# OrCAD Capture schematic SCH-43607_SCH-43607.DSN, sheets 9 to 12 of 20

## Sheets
9 P09_CPU POWER2: size C
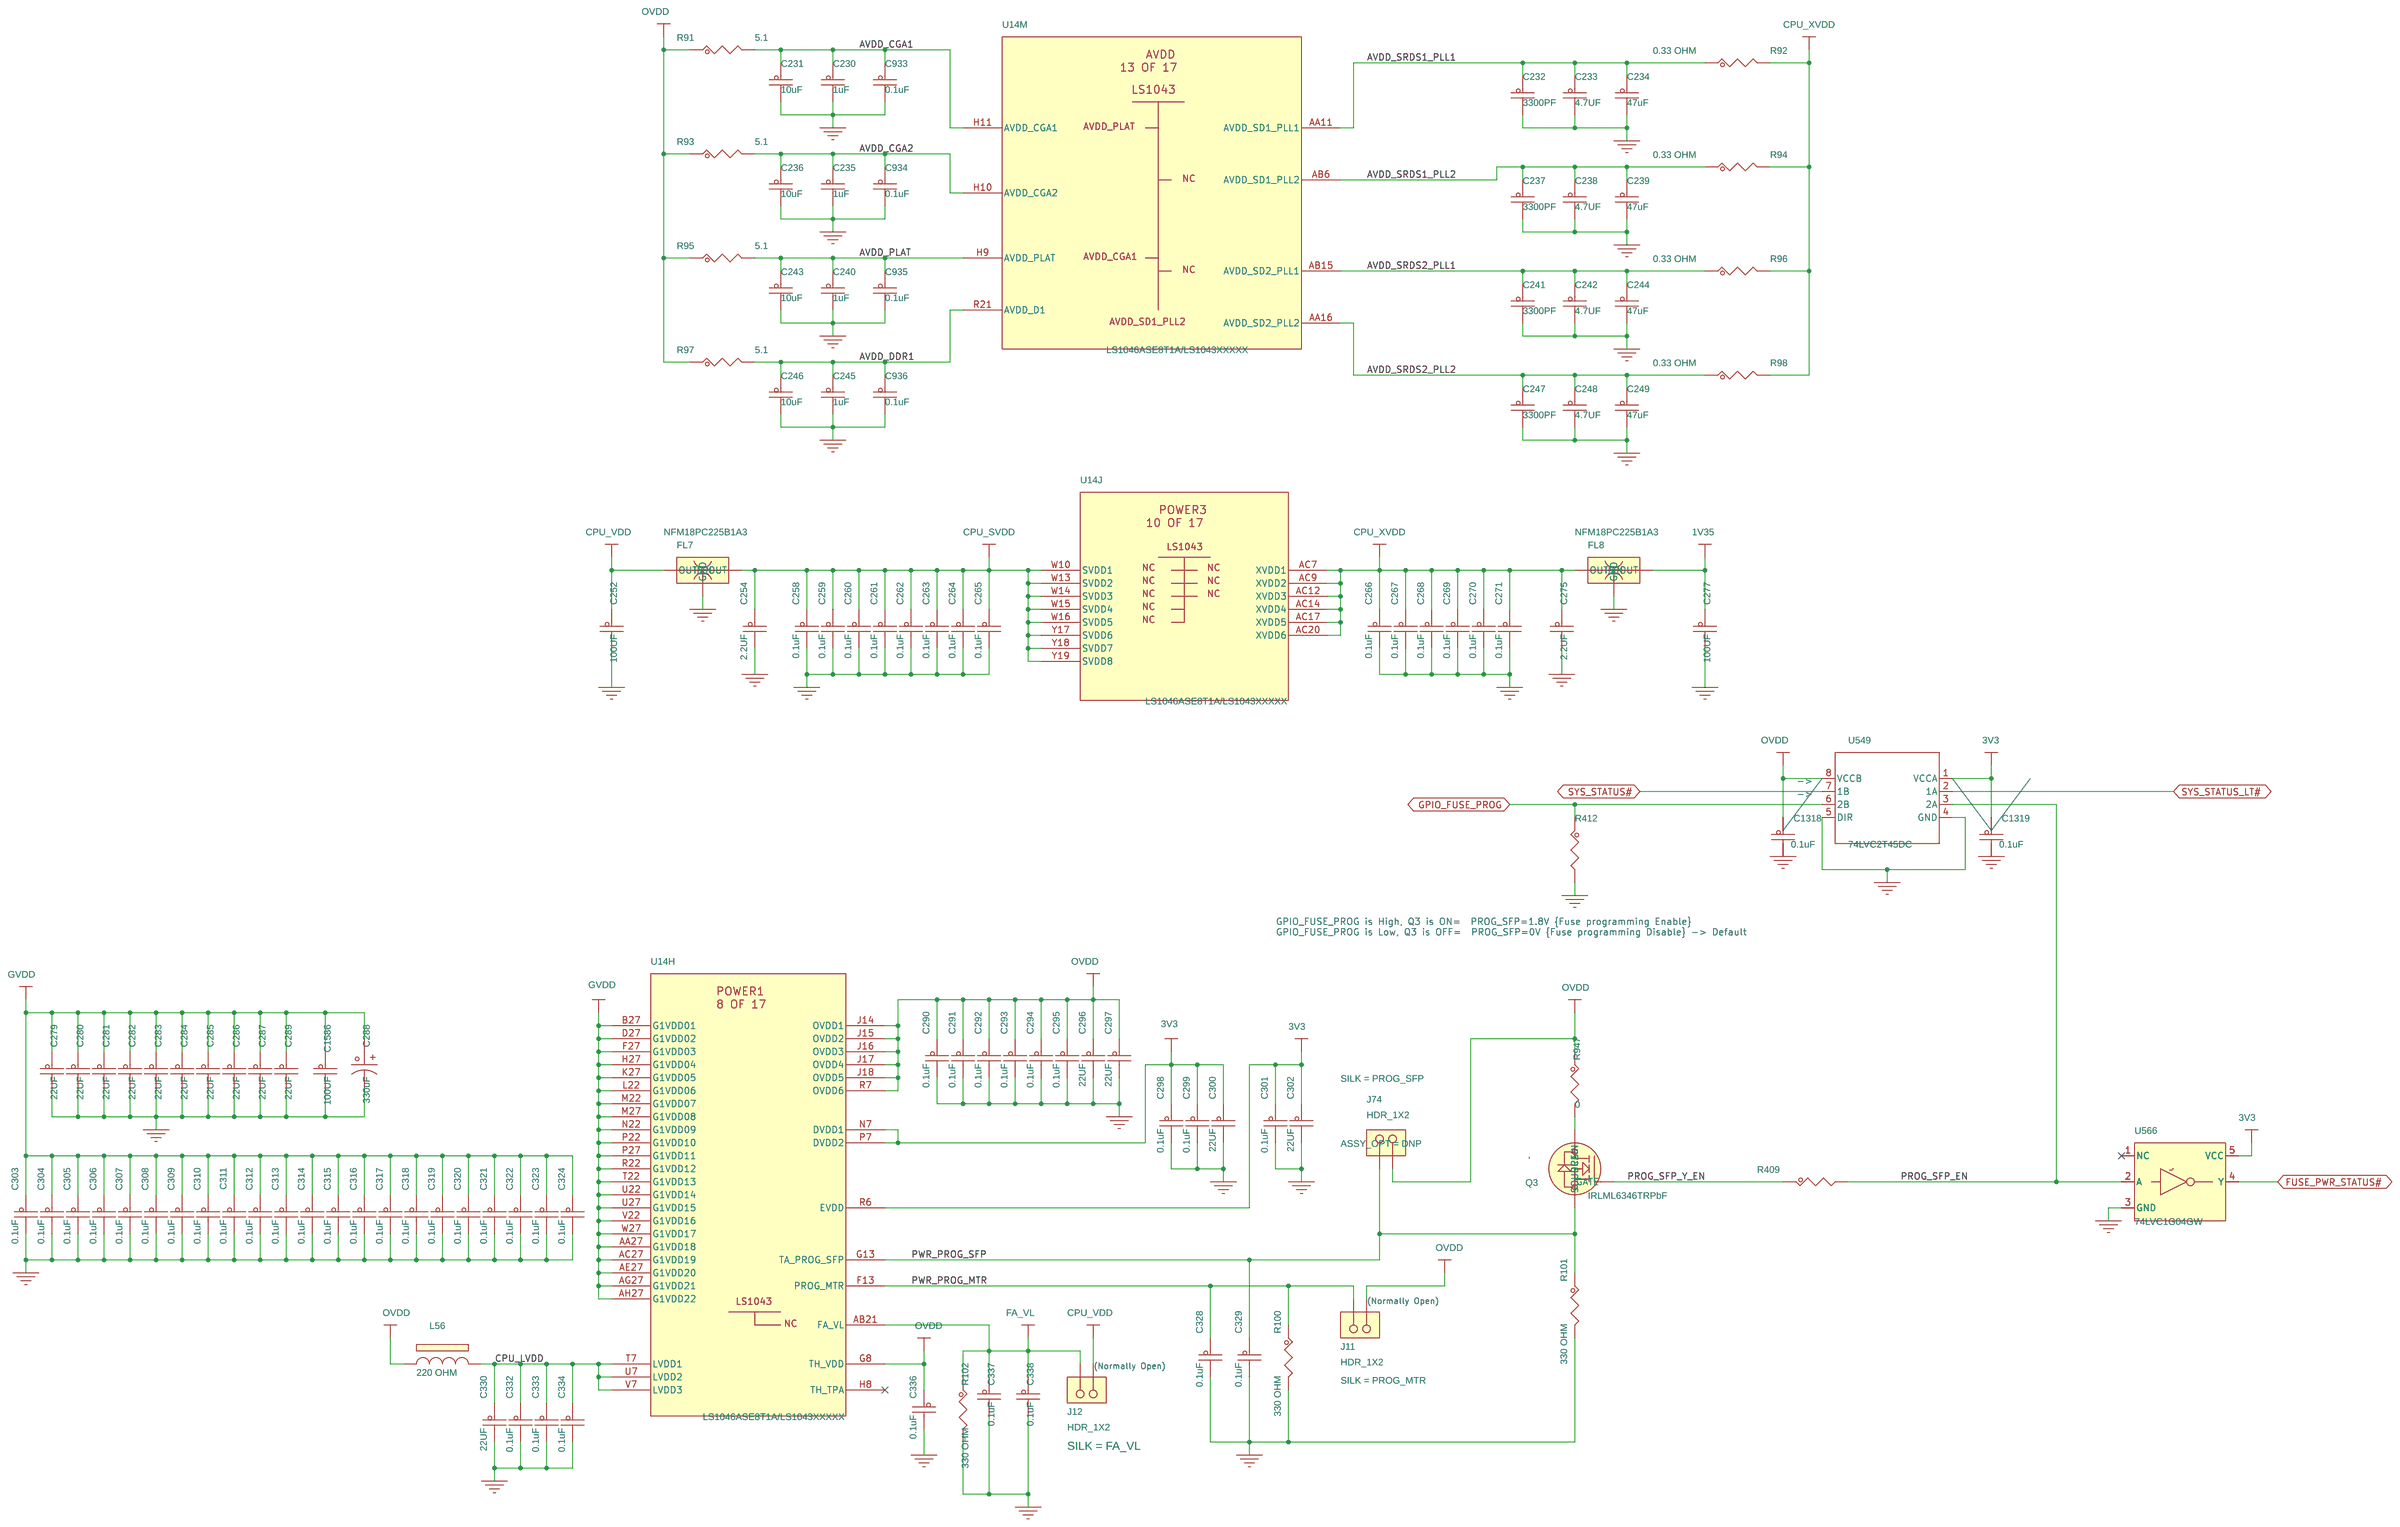
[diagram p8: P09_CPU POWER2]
10 P10_CPU DDR4 CTRL & SDRAM PART1: size C
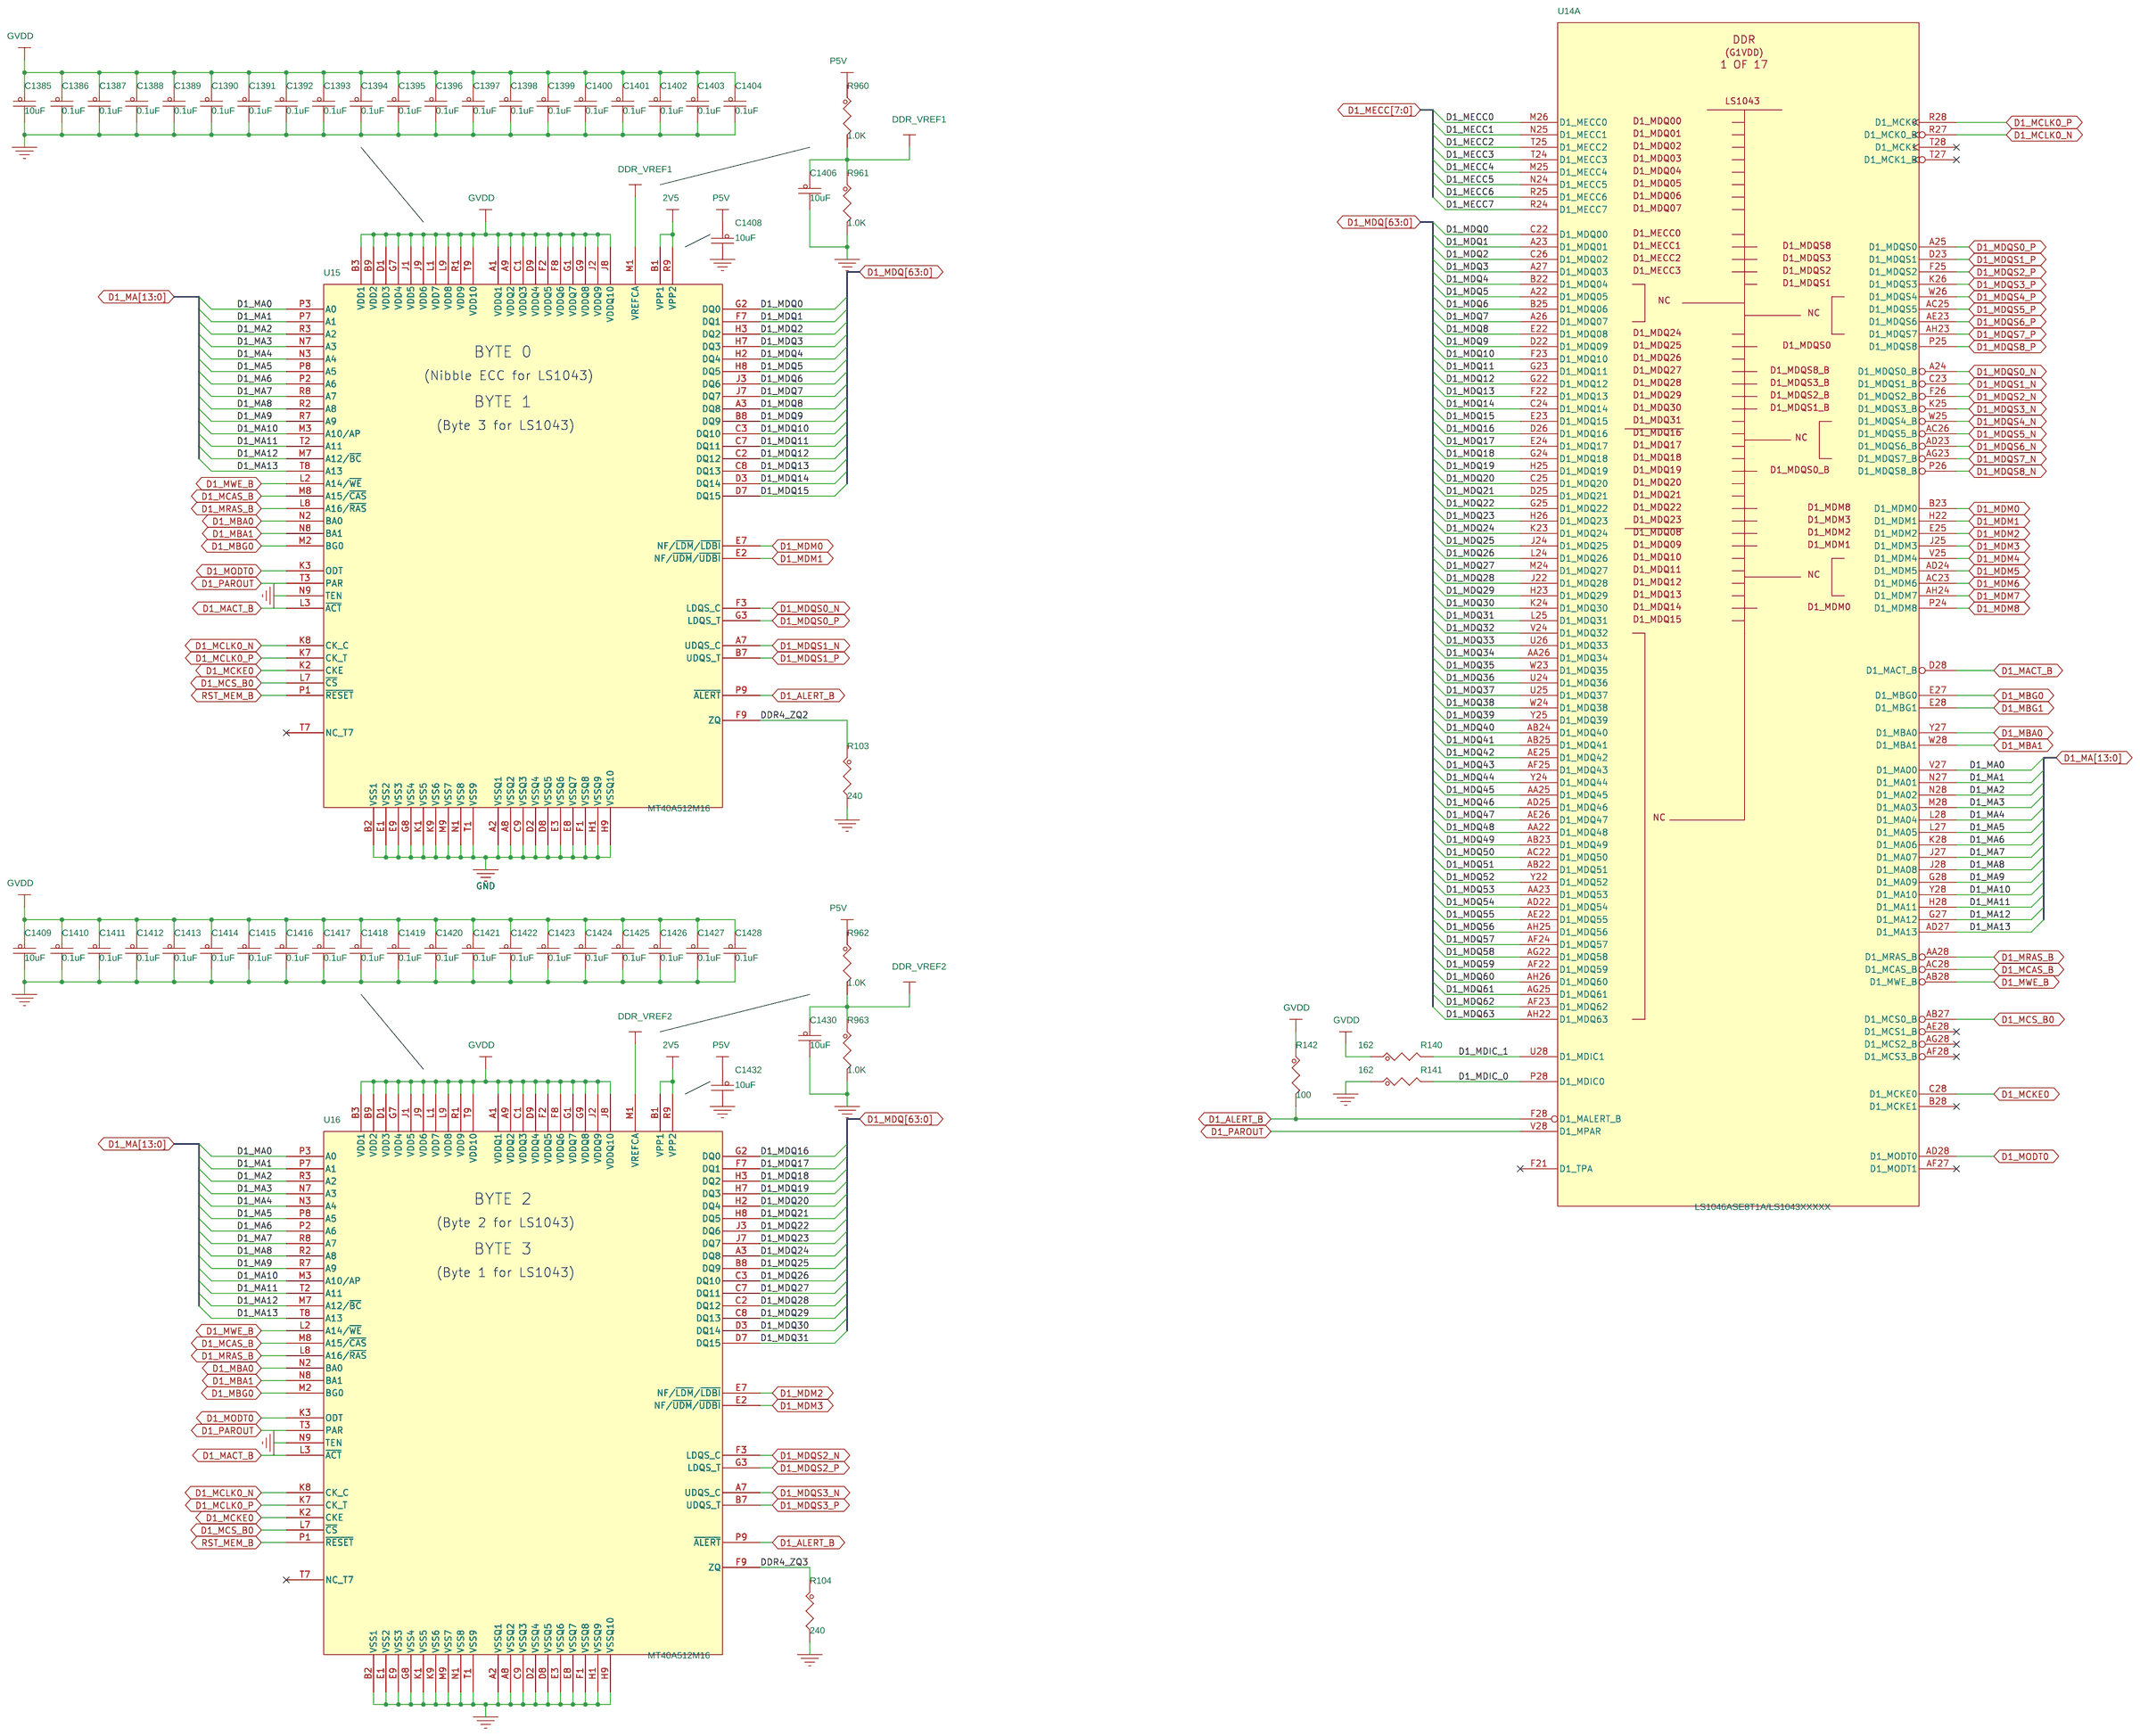
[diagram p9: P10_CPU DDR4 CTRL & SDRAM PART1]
11 P11_DDR4 SDRAM PART2: size C
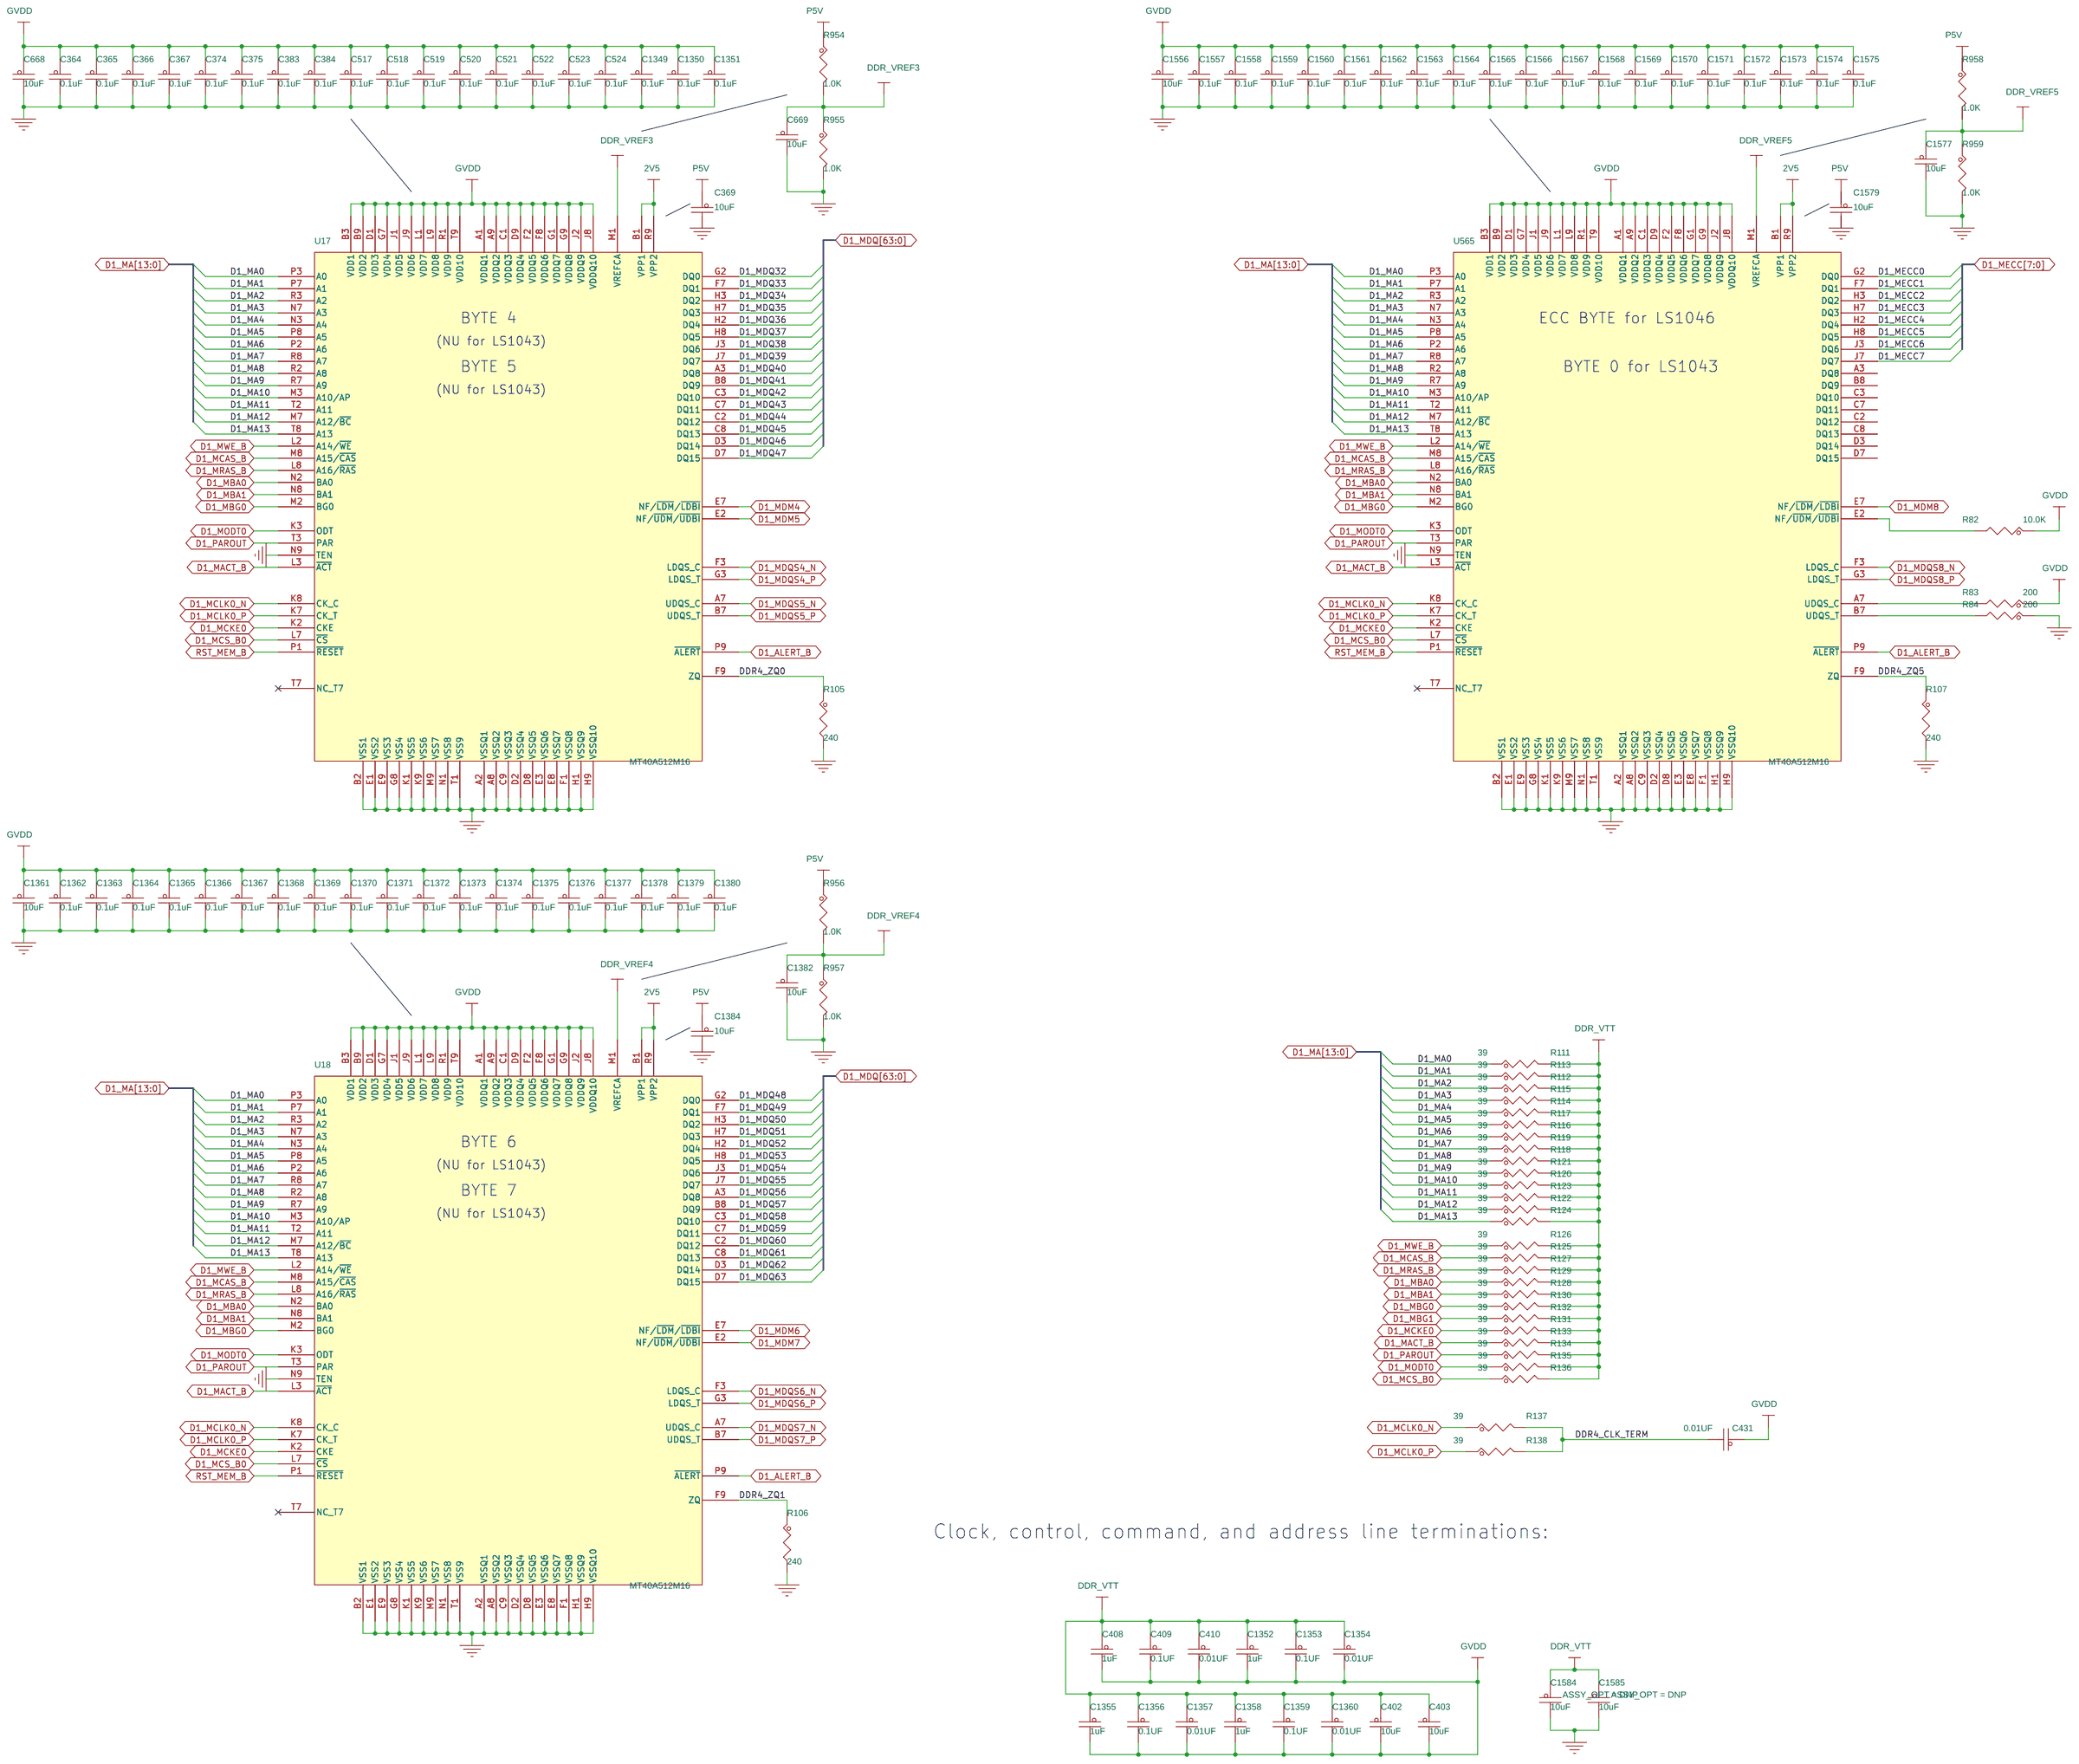
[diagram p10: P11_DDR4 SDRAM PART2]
12 P12_CPU_QSPI & NAND: size C
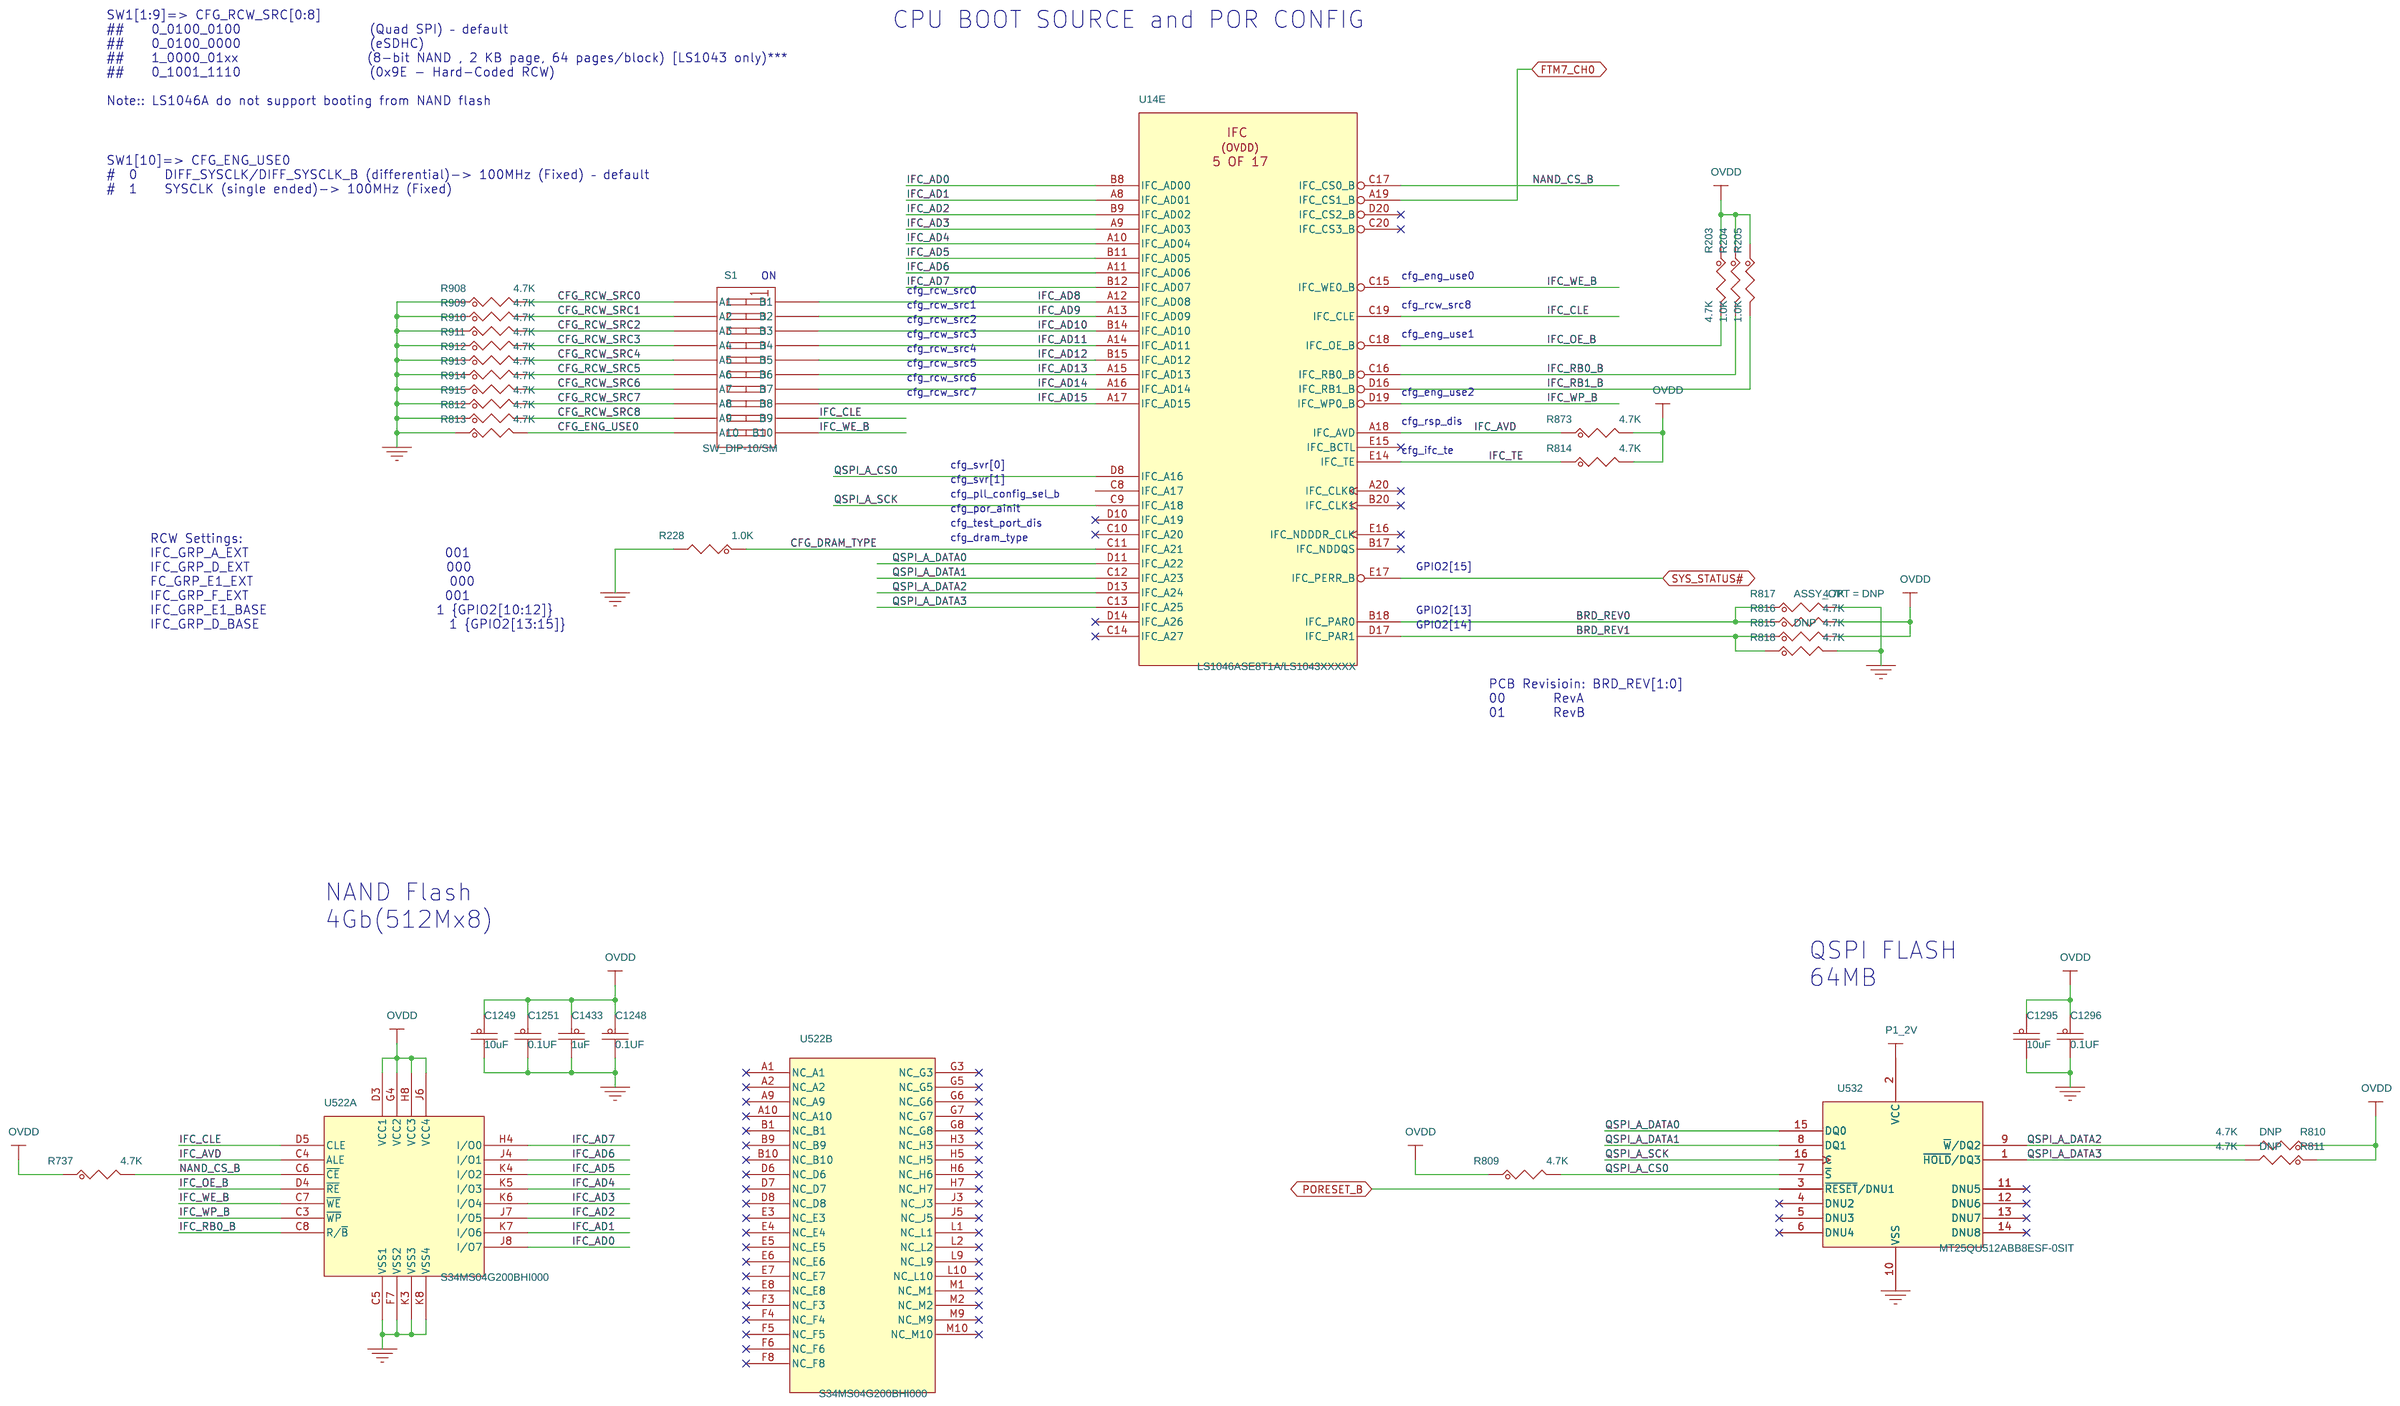
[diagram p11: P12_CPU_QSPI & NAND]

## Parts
sheet P09_CPU POWER2
C230  1uF  [CC0402_25]
C231  10uF  [CC0402_25]
C232  3300PF  [CC0201]
C233  4.7UF  [CC0402_25]
C234  47uF  [CC0603_OV]
C235  1uF  [CC0402_25]
C236  10uF  [CC0402_25]
C237  3300PF  [CC0201]
C238  4.7UF  [CC0402_25]
C239  47uF  [CC0603_OV]
C240  1uF  [CC0402_25]
C241  3300PF  [CC0201]
C242  4.7UF  [CC0402_25]
C243  10uF  [CC0402_25]
C244  47uF  [CC0603_OV]
C245  1uF  [CC0402_25]
C246  10uF  [CC0402_25]
C247  3300PF  [CC0201]
C248  4.7UF  [CC0402_25]
C249  47uF  [CC0603_OV]
C252  100UF  [CC1206_OV]
C254  2.2UF  [CC0402_25]
C258  0.1uF  [CC0201]
C259  0.1uF  [CC0201]
C260  0.1uF  [CC0201]
C261  0.1uF  [CC0201]
C262  0.1uF  [CC0201]
C263  0.1uF  [CC0201]
C264  0.1uF  [CC0201]
C265  0.1uF  [CC0201]
C266  0.1uF  [CC0201]
C267  0.1uF  [CC0201]
C268  0.1uF  [CC0201]
C269  0.1uF  [CC0201]
C270  0.1uF  [CC0201]
C271  0.1uF  [CC0201]
C275  2.2UF  [CC0402_25]
C277  100UF  [CC1206_OV]
C279  22UF  [CC0603_OV]
C280  22UF  [CC0603_OV]
C281  22UF  [CC0603_OV]
C282  22UF  [CC0603_OV]
C283  22UF  [CC0603_OV]
C284  22UF  [CC0603_OV]
C285  22UF  [CC0603_OV]
C286  22UF  [CC0603_OV]
C287  22UF  [CC0603_OV]
C288  330uF  [CC7343-31]
C289  22UF  [CC0603_OV]
C290  0.1uF  [CC0201]
C291  0.1uF  [CC0201]
C292  0.1uF  [CC0201]
C293  0.1uF  [CC0201]
C294  0.1uF  [CC0201]
C295  0.1uF  [CC0201]
C296  22UF  [CC0603_OV]
C297  22UF  [CC0603_OV]
C298  0.1uF  [CC0201]
C299  0.1uF  [CC0201]
C300  22UF  [CC0603_OV]
C301  0.1uF  [CC0201]
C302  22UF  [CC0603_OV]
C303  0.1uF  [CC0201]
C304  0.1uF  [CC0201]
C305  0.1uF  [CC0201]
C306  0.1uF  [CC0201]
C307  0.1uF  [CC0201]
C308  0.1uF  [CC0201]
C309  0.1uF  [CC0201]
C310  0.1uF  [CC0201]
C311  0.1uF  [CC0201]
C312  0.1uF  [CC0201]
C313  0.1uF  [CC0201]
C314  0.1uF  [CC0201]
C315  0.1uF  [CC0201]
C316  0.1uF  [CC0201]
C317  0.1uF  [CC0201]
C318  0.1uF  [CC0201]
C319  0.1uF  [CC0201]
C320  0.1uF  [CC0201]
C321  0.1uF  [CC0201]
C322  0.1uF  [CC0201]
C323  0.1uF  [CC0201]
C324  0.1uF  [CC0201]
C328  0.1uF  [CC0201]
C329  0.1uF  [CC0201]
C330  22UF  [CC0603_OV]
C332  0.1uF  [CC0201]
C333  0.1uF  [CC0201]
C334  0.1uF  [CC0201]
C336  0.1uF  [CC0201]
C337  0.1uF  [CC0201]
C338  0.1uF  [CC0201]
C933  0.1uF  [CC0201]
C934  0.1uF  [CC0201]
C935  0.1uF  [CC0201]
C936  0.1uF  [CC0201]
C1318  0.1uF  [CC0201]
C1319  0.1uF  [CC0201]
C1586  100UF  [CC1206_OV]
FL7  NFM18PC225B1A3  [cc0603_nfm18pc]
FL8  NFM18PC225B1A3  [cc0603_nfm18pc]
J11  HDR_1X2  [hdr1x2_50mil]
J12  HDR_1X2  [hdr1x2_50mil]
J74  HDR_1X2  [hdr1x2_50mil]
L56  220 OHM  [IND_0402]
Q3  IRLML6346TRPbF  [sot23-40x40]
R91  5.1  [RC0402_25]
R92  0.33 OHM  [RC0402_25]
R93  5.1  [RC0402_25]
R94  0.33 OHM  [RC0402_25]
R95  5.1  [RC0402_25]
R96  0.33 OHM  [RC0402_25]
R97  5.1  [RC0402_25]
R98  0.33 OHM  [RC0402_25]
R100  330 OHM  [RC0402_25]
R101  330 OHM  [RC0402_25]
R102  330 OHM  [RC0402_25]
R409  10K  [RC0402_25]
R412  10K  [RC0402_25]
R947  0  [RC0402_25]
U549  74LVC2T45DC  [SSOP8_DCU]
U566  74LVC1G04GW  [sc70-5]
sheet P10_CPU DDR4 CTRL & SDRAM PART1
C1385  10uF  [CC0402_25]
C1386  0.1uF  [CC0201]
C1387  0.1uF  [CC0201]
C1388  0.1uF  [CC0201]
C1389  0.1uF  [CC0201]
C1390  0.1uF  [CC0201]
C1391  0.1uF  [CC0201]
C1392  0.1uF  [CC0201]
C1393  0.1uF  [CC0201]
C1394  0.1uF  [CC0201]
C1395  0.1uF  [CC0201]
C1396  0.1uF  [CC0201]
C1397  0.1uF  [CC0201]
C1398  0.1uF  [CC0201]
C1399  0.1uF  [CC0201]
C1400  0.1uF  [CC0201]
C1401  0.1uF  [CC0201]
C1402  0.1uF  [CC0201]
C1403  0.1uF  [CC0201]
C1404  0.1uF  [CC0201]
C1406  10uF  [CC0402_25]
C1408  10uF  [CC0402_25]
C1409  10uF  [CC0402_25]
C1410  0.1uF  [CC0201]
C1411  0.1uF  [CC0201]
C1412  0.1uF  [CC0201]
C1413  0.1uF  [CC0201]
C1414  0.1uF  [CC0201]
C1415  0.1uF  [CC0201]
C1416  0.1uF  [CC0201]
C1417  0.1uF  [CC0201]
C1418  0.1uF  [CC0201]
C1419  0.1uF  [CC0201]
C1420  0.1uF  [CC0201]
C1421  0.1uF  [CC0201]
C1422  0.1uF  [CC0201]
C1423  0.1uF  [CC0201]
C1424  0.1uF  [CC0201]
C1425  0.1uF  [CC0201]
C1426  0.1uF  [CC0201]
C1427  0.1uF  [CC0201]
C1428  0.1uF  [CC0201]
C1430  10uF  [CC0402_25]
C1432  10uF  [CC0402_25]
R103  240  [RC0402_25]
R104  240  [RC0402_25]
R140  162  [RC0402_25]
R141  162  [RC0402_25]
R142  100  [RC0201]
R960  1.0K  [RC0402_25]
R961  1.0K  [RC0402_25]
R962  1.0K  [RC0402_25]
R963  1.0K  [RC0402_25]
U15  MT40A512M16  [bga96_0p8_8p1x14p1]
U16  MT40A512M16  [bga96_0p8_8p1x14p1]
sheet P11_DDR4 SDRAM PART2
C364  0.1uF  [CC0201]
C365  0.1uF  [CC0201]
C366  0.1uF  [CC0201]
C367  0.1uF  [CC0201]
C369  10uF  [CC0402_25]
C374  0.1uF  [CC0201]
C375  0.1uF  [CC0201]
C383  0.1uF  [CC0201]
C384  0.1uF  [CC0201]
C402  10uF  [CC0402_25]
C403  10uF  [CC0402_25]
C408  1uF  [CC0402_25]
C409  0.1UF  [CC0402_25]
C410  0.01UF  [CC0402_25]
C431  0.01UF  [CC0402_25]
C517  0.1uF  [CC0201]
C518  0.1uF  [CC0201]
C519  0.1uF  [CC0201]
C520  0.1uF  [CC0201]
C521  0.1uF  [CC0201]
C522  0.1uF  [CC0201]
C523  0.1uF  [CC0201]
C524  0.1uF  [CC0201]
C668  10uF  [CC0402_25]
C669  10uF  [CC0402_25]
C1349  0.1uF  [CC0201]
C1350  0.1uF  [CC0201]
C1351  0.1uF  [CC0201]
C1352  1uF  [CC0402_25]
C1353  0.1UF  [CC0402_25]
C1354  0.01UF  [CC0402_25]
C1355  1uF  [CC0402_25]
C1356  0.1UF  [CC0402_25]
C1357  0.01UF  [CC0402_25]
C1358  1uF  [CC0402_25]
C1359  0.1UF  [CC0402_25]
C1360  0.01UF  [CC0402_25]
C1361  10uF  [CC0402_25]
C1362  0.1uF  [CC0201]
C1363  0.1uF  [CC0201]
C1364  0.1uF  [CC0201]
C1365  0.1uF  [CC0201]
C1366  0.1uF  [CC0201]
C1367  0.1uF  [CC0201]
C1368  0.1uF  [CC0201]
C1369  0.1uF  [CC0201]
C1370  0.1uF  [CC0201]
C1371  0.1uF  [CC0201]
C1372  0.1uF  [CC0201]
C1373  0.1uF  [CC0201]
C1374  0.1uF  [CC0201]
C1375  0.1uF  [CC0201]
C1376  0.1uF  [CC0201]
C1377  0.1uF  [CC0201]
C1378  0.1uF  [CC0201]
C1379  0.1uF  [CC0201]
C1380  0.1uF  [CC0201]
C1382  10uF  [CC0402_25]
C1384  10uF  [CC0402_25]
C1556  10uF  [CC0402_25]
C1557  0.1uF  [CC0201]
C1558  0.1uF  [CC0201]
C1559  0.1uF  [CC0201]
C1560  0.1uF  [CC0201]
C1561  0.1uF  [CC0201]
C1562  0.1uF  [CC0201]
C1563  0.1uF  [CC0201]
C1564  0.1uF  [CC0201]
C1565  0.1uF  [CC0201]
C1566  0.1uF  [CC0201]
C1567  0.1uF  [CC0201]
C1568  0.1uF  [CC0201]
C1569  0.1uF  [CC0201]
C1570  0.1uF  [CC0201]
C1571  0.1uF  [CC0201]
C1572  0.1uF  [CC0201]
C1573  0.1uF  [CC0201]
C1574  0.1uF  [CC0201]
C1575  0.1uF  [CC0201]
C1577  10uF  [CC0402_25]
C1579  10uF  [CC0402_25]
C1584  10uF  [CC0402_25]
C1585  10uF  [CC0402_25]
R82  10.0K  [RC0402_25]
R83  200  [RC0402_25]
R84  200  [RC0402_25]
R105  240  [RC0402_25]
R106  240  [RC0402_25]
R107  240  [RC0402_25]
R111  39  [RC0402_25]
R112  39  [RC0402_25]
R113  39  [RC0402_25]
R114  39  [RC0402_25]
R115  39  [RC0402_25]
R116  39  [RC0402_25]
R117  39  [RC0402_25]
R118  39  [RC0402_25]
R119  39  [RC0402_25]
R120  39  [RC0402_25]
R121  39  [RC0402_25]
R122  39  [RC0402_25]
R123  39  [RC0402_25]
R124  39  [RC0402_25]
R125  39  [RC0402_25]
R126  39  [RC0402_25]
R127  39  [RC0402_25]
R128  39  [RC0402_25]
R129  39  [RC0402_25]
R130  39  [RC0402_25]
R131  39  [RC0402_25]
R132  39  [RC0402_25]
R133  39  [RC0402_25]
R134  39  [RC0402_25]
R135  39  [RC0402_25]
R136  39  [RC0402_25]
R137  39  [RC0402_25]
R138  39  [RC0402_25]
R954  1.0K  [RC0402_25]
R955  1.0K  [RC0402_25]
R956  1.0K  [RC0402_25]
R957  1.0K  [RC0402_25]
R958  1.0K  [RC0402_25]
R959  1.0K  [RC0402_25]
U17  MT40A512M16  [bga96_0p8_8p1x14p1]
U18  MT40A512M16  [bga96_0p8_8p1x14p1]
U565  MT40A512M16  [bga96_0p8_8p1x14p1]
sheet P12_CPU_QSPI & NAND
C1248  0.1UF  [CC0402_25]
C1249  10uF  [CC0402_25]
C1251  0.1UF  [CC0402_25]
C1295  10uF  [CC0402_25]
C1296  0.1UF  [CC0402_25]
C1433  1uF  [CC0402_25]
R203  4.7K  [RC0402_25]
R204  1.0K  [RC0402_25]
R205  1.0K  [RC0402_25]
R228  1.0K  [RC0402_25]
R737  4.7K  [RC0402_25]
R809  4.7K  [RC0402_25]
R810  4.7K  [RC0402_25]
R811  4.7K  [RC0402_25]
R812  4.7K  [RC0402_25]
R813  4.7K  [RC0402_25]
R814  4.7K  [RC0402_25]
R815  4.7K  [RC0402_25]
R816  4.7K  [RC0402_25]
R817  4.7K  [RC0402_25]
R818  4.7K  [RC0402_25]
R873  4.7K  [RC0402_25]
R908  4.7K  [RC0402_25]
R909  4.7K  [RC0402_25]
R910  4.7K  [RC0402_25]
R911  4.7K  [RC0402_25]
R912  4.7K  [RC0402_25]
R913  4.7K  [RC0402_25]
R914  4.7K  [RC0402_25]
R915  4.7K  [RC0402_25]
S1  SW_DIP-10/SM  [sw_dip20_10pos_sm]
U522  S34MS04G200BHI000  [vfbga63_0p8_9x11]  (sections A,B)
U532  MT25QU512ABB8ESF-0SIT  [so16w]
sheet P20_SD_SPI_MIKRO_CLICK
U14  LS1046ASE8T1A/LS1043XXXXX  [BGA780_0P8_23X23MM]  (sections A,B,C,D,E,F,G,H,I,J,K,L,M,N,O,P,Q)

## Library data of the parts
C230 C235 C240 C245 = CAP_NP: CAP CER 1uF 25V 10% X5R 0402; AGILE_PN: 150-80001; CAD_APPROVED: Yes; FPLIST: CC0402_25,CC0402_HD,0402_CC; HEIGHT: 0.55MM; MFG_NAME01: MURATA; MFG_PN01: GRM155R61E105KA12; ROHS: Yes; SIGNAL_MODEL: DEFAULT_CAPACITOR_1e+06pF_2_1; Temp_Range: -55°C to +85°C; Tolerance: 10%; VOLTAGE: 25 V
C231 C236 C243 C246 C369 C668 C669 C1249 C1295 C1361 C1382 C1384 C1385 C1406 C1408 C1409 C1430 C1432 C1556 C1577 C1579 = CAP_NP: CAP CER 10UF 6.3V 20% X6S 0402; AGILE_PN: 150-80079; CAD_APPROVED: Yes; FPLIST: CC0402_25,CC0402_HD,0402_CC; HEIGHT: 0.7MM; MFG_NAME01: MURATA; MFG_PN01: GRM155C80J106ME11D; ROHS: Yes; TOL: 10%; Temp_Range: -55 to 105&#8451;; Tolerance: 20%; VOLTAGE: 6.3V
C232 C237 C241 C247 = CAP_NP: CAP CER 3300PF 10V 10% X7R 0201; AGILE_PN: 150-79701; CAD_APPROVED: Yes; FPLIST: CC0201,CC0201_HD,0201_CC; HEIGHT: 0.33MM; MFG_NAME01: MURATA; MFG_PN01: GRM033R71A332KA01D; ROHS: Yes; Tolerance: 10%; VOLTAGE: 10V
C233 C238 C242 C248 = CAP_NP: CAP CER 4.7UF 10V 20% X5R 0402; AGILE_PN: 150-79667; CAD_APPROVED: Yes; FPLIST: CC0402_25,CC0402_HD,0402_CC; HEIGHT: 0.65MM; MFG_NAME01: Murata; MFG_PN01: GRM155R61A475MEAA; ROHS: Yes; SIGNAL_MODEL: DEFAULT_CAPACITOR_4.7e+06pF_2_1; TOL: 10%; Temp_Range: -55 to 85; Tolerance: 20%; VOLTAGE: 10V
C234 C239 C244 C249 = CAP_NP: CAP CER 47UF 6.3V 20% X5R 0603; AGILE_PN: 150-80354; CAD_APPROVED: Yes; FPLIST: CC0603_OV,CC0603,0603_CC; HEIGHT: 1 MM; MFG_NAME01: MURATA; MFG_PN01: GRM188R60J476ME15D; ROHS: Yes; Temp_Range: -55C - 85C; Tolerance: 20%; VOLTAGE: 6.3V
C252 C277 C1586 = CAP_NP: CAP CER 100UF 6.3V 20% X5R 1206; AGILE_PN: 150-77574; CAD_APPROVED: Yes; FPLIST: CC1206_OV,CC1206,1206_CC; HEIGHT: 1.9 MM; MFG_NAME01: Murata; MFG_PN01: GRM31CR60J107ME39L; ROHS: Yes; ROOM: VDD_GVDD_PS; Tolerance: 20%; VOLTAGE: 6.3V
C254 C275 = CAP_NP: CAP CER 2.2UF 10V 20% X5R 0402; AGILE_PN: 150-79665; CAD_APPROVED: Yes; FPLIST: CC0402_25,CC0402_HD,0402_CC; HEIGHT: 0.55 MM; MFG_NAME01: Murata; MFG_PN01: GRM155R61A225ME95; ROHS: Yes; Tolerance: 20%; VOLTAGE: 10V
C258-C271 C290-C295 C298 C299 C301 C303-C324 C328 C329 C332-C334 C336-C338 C364-C367 C374 C375 C383 C384 C517-C524 C933-C936 C1349-C1351 C1362-C1380 C1386-C1404 C1410-C1428 C1557-C1575 = CAP_NP: CAP CER 0.1uF 16V 10% X5R 0201; AGILE_PN: 150-80059; CAD_APPROVED: Yes; FPLIST: CC0201,CC0201_HD,0201_CC; HEIGHT: 0.33MM; MFG_NAME01: MURATA; MFG_PN01: GRM033R61C104KE14D; ROHS: Yes; TOL: 10%; Temp_Range: -55 to +85°C; Tolerance: 10%; VOLTAGE: 16V
C279-C287 C289 C296 C297 = CAP_NP: CAP CER 22UF 6.3V 20% X5R 0603; AGILE_PN: 150-78467; CAD_APPROVED: Yes; FPLIST: CC0603_OV,CC0603,0603_CC; HEIGHT: 1MM; MFG_NAME01: Samsung; MFG_PN01: CL10A226MQ8NRNE; ROHS: Yes; SIGNAL_MODEL: DEFAULT_CAPACITOR_2.2e+07pF_2_1; Tolerance: 20%; VOLTAGE: 6.3V
C288 = CAP_POL: CAP POLM TANT ESR 0.009 OHMS 330uF 6.3V 20% -- 7343-31; AGILE_PN: 150-80316; CAD_APPROVED: Yes; HEIGHT: 3.1MM; MFG_NAME01: KEMET; MFG_PN01: T520D337M006ATE009; ROHS: Yes; Temp_Range: -55°C ~ 105°C; Tolerance: 20%; VOLTAGE: 6.3V
C300 C302 C330 = CAP_NP: CAP CER 22UF 6.3V 20% X5R 0603; AGILE_PN: 150-78467; CAD_APPROVED: Yes; FPLIST: CC0603_OV,CC0603,0603_CC; HEIGHT: 1MM; MFG_NAME01: Samsung; MFG_PN01: CL10A226MQ8NRNE; ROHS: Yes; SIGNAL_MODEL: DEFAULT_CAPACITOR_2.2e+07pF_2_1; TOL: 20%; Tolerance: 20%; VOLTAGE: 6.3V
C1318 C1319 = CAP_NP: CAP CER 0.1uF 16V 10% X5R 0201; AGILE_PN: 150-80059; CAD_APPROVED: Yes; FPLIST: CC0201,CC0201_HD,0201_CC; HEIGHT: 0.33MM; MFG_NAME01: MURATA; MFG_PN01: GRM033R61C104KE14D; ROHS: Yes; Temp_Range: -55 to +85°C; Tolerance: 10%; VOLTAGE: 16V
FL7 FL8 = NFM18PC225B1A3: CAP FILTER EMI 2.2uF 10V 20% -- 0603; AGILE_PN: 150-79428; CAD_APPROVED: Yes; HEIGHT: 0.9MM; MFG_NAME01: MURATA; MFG_PN01: NFM18PC225B1A3D; ROHS: Yes; ROOM: DUT_CLOSE; Temp_Range: -40 C to +85 C; Tolerance: 20%; VOLTAGE: 10V
J11 = CONN_HDR_2X1: HDR 1X2 TH 50MIL SP 165H AU 91L; AGILE_PN: 210-80212; CAD_APPROVED: Yes; HEIGHT: 4.2MM; MFG_NAME01: SULLINS ELECTRONICS CORP; MFG_PN01: GRPB021VWVN-RC; ROHS: Yes; SILK: PROG_MTR
J12 = CONN_HDR_2X1: HDR 1X2 TH 50MIL SP 165H AU 91L; AGILE_PN: 210-80212; CAD_APPROVED: Yes; HEIGHT: 4.2MM; MFG_NAME01: SULLINS ELECTRONICS CORP; MFG_PN01: GRPB021VWVN-RC; ROHS: Yes; SILK: FA_VL
J74 = CONN_HDR_2X1: HDR 1X2 TH 50MIL SP 165H AU 91L; AGILE_PN: 210-80212; ASSY_OPT: DNP; CAD_APPROVED: Yes; HEIGHT: 4.2MM; MFG_NAME01: SULLINS ELECTRONICS CORP; MFG_PN01: GRPB021VWVN-RC; ROHS: Yes; SILK: PROG_SFP
L56 = INDUCTOR_FERRITE: IND FER BEAD 220 OHM@100MHZ 0.3A 25% 0.35 OHM 0402; AGILE_PN: 180-77772; CAD_APPROVED: Yes; FPLIST: IND_0402,0402_CC; HEIGHT: 0.55MM; MFG_NAME01: Murata; MFG_PN01: BLM15AG221SN1D; PART_TYPE: FERRITE\BEAD; ROHS: Yes; TOL: 25%; Tolerance: 25%
Q3 = MOSFET_N: TRAN NMOS PWR 3.4A 30V SOT-23; AGILE_PN: 480-78399; CAD_APPROVED: Yes; HEIGHT: 1.12 MM; MFG_NAME01: International Rectifier; ROHS: Yes
R91 R93 R95 R97 = RES: RES MF 5.10 OHM 1/16W 1% 0402; AGILE_PN: 470-30609; CAD_APPROVED: Yes; FPLIST: RC0402_25,RC0402_HD,0402_CC; HEIGHT: 0.40 MM; MFG_NAME01: WALSIN TECHNOLOGY CORP.; MFG_PN01: WR04W5R10FTL; ROHS: Yes; Tolerance: 1%
R92 R94 R96 R98 = RES: RES MF 0.33 OHM 1/8W 1% 0402; AGILE_PN: 470-80356; CAD_APPROVED: Yes; FPLIST: RC0402_25,RC0402_HD,0402_CC; HEIGHT: 0.4MM; MFG_NAME01: Panasonic; MFG_PN01: ERJ2BQFR33X; ROHS: Yes
R100-R102 = RES: RES MF 330 OHM 1/16W 1% 0402; AGILE_PN: 470-80566; CAD_APPROVED: Yes; FPLIST: RC0402_25,RC0402_HD,0402_CC; HEIGHT: 0.4MM; MFG_NAME01: WALSIN TECHNOLOGY CORP.; MFG_PN01: WR04X3300FTL; ROHS: Yes; Tolerance: 1%
R409 R412 = RES: RES MF 10K 1/5W 1% AEC-Q200 0402; AGILE_PN: 470-80881; CAD_APPROVED: Yes; FPLIST: RC0402_25,RC0402_HD,0402_CC; HEIGHT: 0.4MM; MFG_NAME01: VISHAY INTERTECHNOLOGY; MFG_PN01: CRCW040210K0FKEDHP; ROHS: Yes; Temp_Range: -55&#8451; to 155&#8451;; Tolerance: 1%
R947 = RES: RES MF ZERO OHM 1/10W -- 0402; AGILE_PN: 470-79965; CAD_APPROVED: Yes; FPLIST: RC0402_25,RC0402_HD,RC0402_X2,0402_CC; HEIGHT: 0.4MM; MFG_NAME01: Panasonic; MFG_PN01: ERJ-2GE0R00X; ROHS: Yes
U549 = 74LVC2T45DC_8P: IC TRANSLATING XCVR DUAL BIT/SUPPLY TS 1.2-5.5V VSSOP8; AGILE_PN: 312-81751; CAD_APPROVED: Yes; HEIGHT: 1MM; MFG_NAME01: NEXPERIA; ROHS: Yes; Temp_Range: -40°C to +125°C
U566 = NC7SZ14: IC INV SGL 1.65-5.5V TSSOP5; AGILE_PN: 315-81077; CAD_APPROVED: Yes; HEIGHT: 1.1MM; MFG_NAME01: NEXPERIA; MFG_PN01: 74LVC1G04GW,125; ROHS: Yes
R103-R107 = RES: RES MF 240 OHM 1/16W 1% 0402; AGILE_PN: 470-30776; CAD_APPROVED: Yes; FPLIST: RC0402_25,RC0402_HD,0402_CC; HEIGHT: 0.40 MM; MFG_NAME01: WALSIN TECHNOLOGY CORP.; MFG_PN01: WR04X2400FTL; ROHS: Yes; Tolerance: 1%
R140 R141 = RES: RES MF 162 OHM 1/16W 1% 0402; AGILE_PN: 470-80834; CAD_APPROVED: Yes; FPLIST: RC0402_25,RC0402_HD,0402_CC; HEIGHT: 0.4MM; MFG_NAME01: WALSIN TECHNOLOGY CORP.; MFG_PN01: WR04X1620FTL; ROHS: Yes; Tolerance: 1%
R142 = RES: RES MF 100 OHM 1/20W 1% AEC-Q200 0201; AGILE_PN: 470-81361; CAD_APPROVED: Yes; FPLIST: RC0201,0201_CC; HEIGHT: 0.26 MM; MFG_NAME01: YAGEO AMERICA; MFG_PN01: AC0201FR-07100RL; ROHS: Yes; Temp_Range: -55&#8451; to 155&#8451;
R204 R205 R228 R954-R963 = RES: RES MF 1.0K 1/16W 1% 0402; AGILE_PN: 470-76037; CAD_APPROVED: Yes; FPLIST: RC0402_25,RC0402_HD,RC0402_X2,0402_CC; HEIGHT: 0.4MM; MFG_NAME01: YAGEO AMERICA; MFG_PN01: RC0402FR-071KL; ROHS: Yes; Tolerance: 1%
U15-U18 U565 = MT40A512M16JY_BGA96: IC MEM DDR4 SDRAM 8Gb 512MX16 1200MHZ 0.833NS 1.2V FBGA96; AGILE_PN: 334-77724; CAD_APPROVED: Yes; HEIGHT: 1.2MM; MFG_NAME01: MICRON; MFG_PN01: MT40A512M16JY-083E:B; ROHS: Yes; Temp_Range: 0 to + 95 °C
C402 C403 = CAP_NP: CAP CER 10UF 6.3V 20% X6S 0402; AGILE_PN: 150-80079; CAD_APPROVED: Yes; FPLIST: CC0402_25,CC0402_HD,0402_CC; HEIGHT: 0.7MM; MFG_NAME01: MURATA; MFG_PN01: GRM155C80J106ME11D; ROHS: Yes; ROOM: DDR_DIMM; Temp_Range: -55 to 105&#8451;; Tolerance: 20%; VOLTAGE: 6.3V
C408 C1352 C1355 C1358 C1433 = CAP_NP: CAP CER 1uF 25V 10% X5R 0402; AGILE_PN: 150-80001; CAD_APPROVED: Yes; FPLIST: CC0402_25,CC0402_HD,0402_CC; HEIGHT: 0.55MM; MFG_NAME01: MURATA; MFG_PN01: GRM155R61E105KA12; ROHS: Yes; SIGNAL_MODEL: DEFAULT_CAPACITOR_1e+06pF_2_1; TOL: 10%; Temp_Range: -55°C to +85°C; Tolerance: 10%; VOLTAGE: 25 V; WVDC: 10V
C409 C1353 C1356 C1359 = CAP_NP: CAP CER 0.1UF 25V 10% X5R 0402; AGILE_PN: 150-80045; CAD_APPROVED: Yes; FPLIST: CC0402_25,CC0402_HD,0402_CC; HEIGHT: 0.55MM; MFG_NAME01: Samsung Electro Mechanics; MFG_PN01: CL05A104KA5NNNC; ROHS: Yes; SIGNAL_MODEL: DEFAULT_CAPACITOR_100000pF_2_1; TOL: 10%; Tolerance: 10%; VOLTAGE: 25V
C410 C431 C1354 C1357 C1360 = CAP_NP: CAP CER 0.01UF 50V 10% X7R 0402; AGILE_PN: 150-30114; CAD_APPROVED: Yes; FPLIST: CC0402_25,CC0402_HD,0402_CC; HEIGHT: 0.74 MM; MFG_NAME01: WALSIN TECHNOLOGY CORP.; MFG_PN01: 0402B103K500CT; ROHS: Yes; SIGNAL_MODEL: DEFAULT_CAPACITOR_10000pF_2_1; Tolerance: 10%; VOLTAGE: 50V
C1584 C1585 = CAP_NP: CAP CER 10UF 6.3V 20% X6S 0402; AGILE_PN: 150-80079; ASSY_OPT: DNP; CAD_APPROVED: Yes; FPLIST: CC0402_25,CC0402_HD,0402_CC; HEIGHT: 0.7MM; MFG_NAME01: MURATA; MFG_PN01: GRM155C80J106ME11D; ROHS: Yes; ROOM: DDR_DIMM; Temp_Range: -55 to 105&#8451;; Tolerance: 20%; VOLTAGE: 6.3V
R82 = RES: RES MF 10.0K 1/16W 1% 0402; AGILE_PN: 470-80574; CAD_APPROVED: Yes; FPLIST: RC0402_25,RC0402_HD,0402_CC; HEIGHT: 0.4MM; MFG_NAME01: WALSIN TECHNOLOGY CORP.; MFG_PN01: WR04X1002FTL; ROHS: Yes; Tolerance: 1%
R83 R84 = RES: RES MF 200 OHM 1/10W 1% 0402; AGILE_PN: 470-80287; CAD_APPROVED: Yes; FPLIST: RC0402_25,RC0402_HD,0402_CC; HEIGHT: 0.4 MM; MFG_NAME01: Panasonic; MFG_PN01: ERJ2RKF2000X; ROHS: Yes; Tolerance: 1%
R111-R138 = RES: RES MF 39 OHM 1/16W 1% 0402; AGILE_PN: 470-30699; CAD_APPROVED: Yes; FPLIST: RC0402_25,RC0402_HD,0402_CC; HEIGHT: 0.40 MM; MFG_NAME01: YAGEO AMERICA; MFG_PN01: RC0402FR-0739RL; ROHS: Yes; Temp_Range: -55°C ~ 155°C; Tolerance: 1%
C1248 C1251 C1296 = CAP_NP: CAP CER 0.1UF 25V 10% X5R 0402; AGILE_PN: 150-80045; CAD_APPROVED: Yes; FPLIST: CC0402_25,CC0402_HD,0402_CC; HEIGHT: 0.55MM; MFG_NAME01: Samsung Electro Mechanics; MFG_PN01: CL05A104KA5NNNC; ROHS: Yes; TOL: 10%; Tolerance: 10%; VOLTAGE: 25V
R203 R737 R809 R812-R814 R816 R818 R873 R908-R915 = RES: RES MF 4.70K 1/16W 1% 0402; AGILE_PN: 470-75418; CAD_APPROVED: Yes; FPLIST: RC0402_25,RC0402_HD,0402_CC; HEIGHT: 0.4mm; MFG_NAME01: WALSIN TECHNOLOGY CORP.; MFG_PN01: WR04X4701FTL; ROHS: Yes; Tolerance: 1%
R810 R811 R815 R817 = RES: RES MF 4.70K 1/16W 1% 0402; AGILE_PN: 470-75418; ASSY_OPT: DNP; CAD_APPROVED: Yes; FPLIST: RC0402_25,RC0402_HD,0402_CC; HEIGHT: 0.4mm; MFG_NAME01: WALSIN TECHNOLOGY CORP.; MFG_PN01: WR04X4701FTL; ROHS: Yes; Tolerance: 1%
S1 = SW_DIP-10: SW SPST DIP 10POS 100MA 50V SMT; AGILE_PN: 510-77745; CAD_APPROVED: Yes; HEIGHT: 2.65MM; MFG_NAME01: CTS; MFG_PN01: 218-10LPST; ROHS: Yes
U522 = S34MS04G200BH_BGA63P: IC MEM NAND FLASH 512MX8 1.8V BGA63; AGILE_PN: 342-00607; CAD_APPROVED: Yes; HEIGHT: 1 MM; MFG_NAME01: SPANSION LLC; ROHS: Yes
U532 = MT25QU512ABB8ESF_SO16W: IC MEM FLASH SERIAL NOR 512MB 166MHZ 1.7-2V SOIC16; AGILE_PN: 342-00681; CAD_APPROVED: Yes; HEIGHT: 2.65MM; MFG_NAME01: MICRON; ROHS: Yes
U14 = LS1043_1046_SS: IC MCU LS1046 and LS1043 FBGA780; AGILE_PN: TMP-WF-33894; CAD_APPROVED: Yes; HEIGHT: 2.61/2.07MM; MFG_NAME01: NXP SEMICONDUCTORS; PRE_APN: 344-02328; ROHS: Yes

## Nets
1V35: C277.1 FL8.1(IN_OUT) ; also on sheet 6
2V5: C369.1 C1384.1 C1408.1 C1432.1 C1579.1 U15.B1(VPP1) U15.R9(VPP2) U16.B1(VPP1) U16.R9(VPP2) U17.B1(VPP1) U17.R9(VPP2) U18.B1(VPP1) U18.R9(VPP2) U565.B1(VPP1) U565.R9(VPP2) ; also on sheet 6 8 15 18
3V3: C298.1 C299.1 C300.1 C301.1 C302.1 C1319.1 U14.N7(DVDD1) U14.P7(DVDD2) U14.R6(EVDD) U549.1(VCCA) U566.5(VCC) ; also on sheet 5 6 7 8 13 14 16 17 18 19 20
AVDD_CGA1: C230.1 C231.1 C933.1 R91.2 U14.H11(AVDD_CGA1)
AVDD_CGA2: C235.1 C236.1 C934.1 R93.2 U14.H10(AVDD_CGA2)
AVDD_DDR1: C245.1 C246.1 C936.1 R97.2 U14.R21(AVDD_D1)
AVDD_PLAT: C240.1 C243.1 C935.1 R95.2 U14.H9(AVDD_PLAT)
AVDD_SRDS1_PLL1: C232.1 C233.1 C234.1 R92.1 U14.AA11(AVDD_SD1_PLL1)
AVDD_SRDS1_PLL2: C237.1 C238.1 C239.1 R94.1 U14.AB6(AVDD_SD1_PLL2)
AVDD_SRDS2_PLL1: C241.1 C242.1 C244.1 R96.1 U14.AB15(AVDD_SD2_PLL1)
AVDD_SRDS2_PLL2: C247.1 C248.1 C249.1 R98.1 U14.AA16(AVDD_SD2_PLL2)
GND: C230.2 C231.2 C232.2 C233.2 C234.2 C235.2 C236.2 C237.2 C238.2 C239.2 C240.2 C241.2 C242.2 C243.2 C244.2 C245.2 C246.2 C247.2 C248.2 C249.2 C252.2 C254.2 C258.2 C259.2 C260.2 C261.2 C262.2 C263.2 C264.2 C265.2 C266.2 C267.2 C268.2 C269.2 C270.2 C271.2 C275.2 C277.2 C279.2 C280.2 C281.2 C282.2 C283.2 C284.2 C285.2 C286.2 C287.2 C288.2 C289.2 C290.2 C291.2 C292.2 C293.2 C294.2 C295.2 C296.2 C297.2 C298.2 C299.2 C300.2 C301.2 C302.2 C303.2 C304.2 C305.2 C306.2 C307.2 C308.2 C309.2 C310.2 C311.2 C312.2 C313.2 C314.2 C315.2 C316.2 C317.2 C318.2 C319.2 C320.2 C321.2 C322.2 C323.2 C324.2 C328.2 C329.2 C330.2 C332.2 C333.2 C334.2 C336.2 C337.2 C338.2 C364.2 C365.2 C366.2 C367.2 C369.2 C374.2 C375.2 C383.2 C384.2 C517.2 C518.2 C519.2 C520.2 C521.2 C522.2 C523.2 C524.2 C668.2 C669.2 C933.2 C934.2 C935.2 C936.2 C1248.2 C1249.2 C1251.2 C1295.2 C1296.2 C1318.2 C1319.2 C1349.2 C1350.2 C1351.2 C1361.2 C1362.2 C1363.2 C1364.2 C1365.2 C1366.2 C1367.2 C1368.2 C1369.2 C1370.2 C1371.2 C1372.2 C1373.2 C1374.2 C1375.2 C1376.2 C1377.2 C1378.2 C1379.2 C1380.2 C1382.2 C1384.2 C1385.2 C1386.2 C1387.2 C1388.2 C1389.2 C1390.2 C1391.2 C1392.2 C1393.2 C1394.2 C1395.2 C1396.2 C1397.2 C1398.2 C1399.2 C1400.2 C1401.2 C1402.2 C1403.2 C1404.2 C1406.2 C1408.2 C1409.2 C1410.2 C1411.2 C1412.2 C1413.2 C1414.2 C1415.2 C1416.2 C1417.2 C1418.2 C1419.2 C1420.2 C1421.2 C1422.2 C1423.2 C1424.2 C1425.2 C1426.2 C1427.2 C1428.2 C1430.2 C1432.2 C1433.2 C1556.2 C1557.2 C1558.2 C1559.2 C1560.2 C1561.2 C1562.2 C1563.2 C1564.2 C1565.2 C1566.2 C1567.2 C1568.2 C1569.2 C1570.2 C1571.2 C1572.2 C1573.2 C1574.2 C1575.2 C1577.2 C1579.2 C1584.2 C1585.2 C1586.2 FL7.2(GND) FL8.2(GND) R84.1 R100.2 R101.2 R102.2 R103.2 R104.2 R105.2 R106.2 R107.2 R141.1 R228.2 R412.2 R812.1 R813.1 R817.2 R818.2 R908.1 R909.1 R910.1 R911.1 R912.1 R913.1 R914.1 R915.1 R955.2 R957.2 R959.2 R961.2 R963.2 U15.A2(VSSQ1) U15.A8(VSSQ2) U15.B2(VSS1) U15.C9(VSSQ3) U15.D2(VSSQ4) U15.D8(VSSQ5) U15.E1(VSS2) U15.E3(VSSQ6) U15.E8(VSSQ7) U15.E9(VSS3) U15.F1(VSSQ8) U15.G8(VSS4) U15.H1(VSSQ9) U15.H9(VSSQ10) U15.K1(VSS5) U15.K9(VSS6) U15.M9(VSS7) U15.N1(VSS8) U15.N9(TEN) U15.T1(VSS9) U16.A2(VSSQ1) U16.A8(VSSQ2) U16.B2(VSS1) U16.C9(VSSQ3) U16.D2(VSSQ4) U16.D8(VSSQ5) U16.E1(VSS2) U16.E3(VSSQ6) U16.E8(VSSQ7) U16.E9(VSS3) U16.F1(VSSQ8) U16.G8(VSS4) U16.H1(VSSQ9) U16.H9(VSSQ10) U16.K1(VSS5) U16.K9(VSS6) U16.M9(VSS7) U16.N1(VSS8) U16.N9(TEN) U16.T1(VSS9) U17.A2(VSSQ1) U17.A8(VSSQ2) U17.B2(VSS1) U17.C9(VSSQ3) U17.D2(VSSQ4) U17.D8(VSSQ5) U17.E1(VSS2) U17.E3(VSSQ6) U17.E8(VSSQ7) U17.E9(VSS3) U17.F1(VSSQ8) U17.G8(VSS4) U17.H1(VSSQ9) U17.H9(VSSQ10) U17.K1(VSS5) U17.K9(VSS6) U17.M9(VSS7) U17.N1(VSS8) U17.N9(TEN) U17.T1(VSS9) U18.A2(VSSQ1) U18.A8(VSSQ2) U18.B2(VSS1) U18.C9(VSSQ3) U18.D2(VSSQ4) U18.D8(VSSQ5) U18.E1(VSS2) U18.E3(VSSQ6) U18.E8(VSSQ7) U18.E9(VSS3) U18.F1(VSSQ8) U18.G8(VSS4) U18.H1(VSSQ9) U18.H9(VSSQ10) U18.K1(VSS5) U18.K9(VSS6) U18.M9(VSS7) U18.N1(VSS8) U18.N9(TEN) U18.T1(VSS9) U522.C5(VSS1) U522.F7(VSS2) U522.K3(VSS3) U522.K8(VSS4) U532.10(VSS) U549.4(GND) U549.5(DIR) U565.A2(VSSQ1) U565.A8(VSSQ2) U565.B2(VSS1) U565.C9(VSSQ3) U565.D2(VSSQ4) U565.D8(VSSQ5) U565.E1(VSS2) U565.E3(VSSQ6) U565.E8(VSSQ7) U565.E9(VSS3) U565.F1(VSSQ8) U565.G8(VSS4) U565.H1(VSSQ9) U565.H9(VSSQ10) U565.K1(VSS5) U565.K9(VSS6) U565.M9(VSS7) U565.N1(VSS8) U565.N9(TEN) U565.T1(VSS9) U566.3(GND) ; also on sheet 5 6 7 8 13 14 15 16 17 18 19 20
BRD_REV0: R816.1 R817.1 U14.B18(IFC_PAR0)
BRD_REV1: R815.1 R818.1 U14.D17(IFC_PAR1)
CFG_DRAM_TYPE: R228.1 U14.C11(IFC_A21)
CFG_ENG_USE0: R813.2 S1.10(A10)
CFG_RCW_SRC0: R908.2 S1.1(A1)
CFG_RCW_SRC1: R909.2 S1.2(A2)
CFG_RCW_SRC2: R910.2 S1.3(A3)
CFG_RCW_SRC3: R911.2 S1.4(A4)
CFG_RCW_SRC4: R912.2 S1.5(A5)
CFG_RCW_SRC5: R913.2 S1.6(A6)
CFG_RCW_SRC6: R914.2 S1.7(A7)
CFG_RCW_SRC7: R915.2 S1.8(A8)
CFG_RCW_SRC8: R812.2 S1.9(A9)
CPU_LVDD: C330.1 C332.1 C333.1 C334.1 L56.2 U14.T7(LVDD1) U14.U7(LVDD2) U14.V7(LVDD3)
CPU_SVDD: C254.1 C258.1 C259.1 C260.1 C261.1 C262.1 C263.1 C264.1 C265.1 FL7.1(IN_OUT) U14.W10(SVDD1) U14.W13(SVDD2) U14.W14(SVDD3) U14.W15(SVDD4) U14.W16(SVDD5) U14.Y17(SVDD6) U14.Y18(SVDD7) U14.Y19(SVDD8) ; also on sheet 13
CPU_VDD: C252.1 FL7.3(OUT_IN) J12.1 ; also on sheet 7 8
CPU_XVDD: C266.1 C267.1 C268.1 C269.1 C270.1 C271.1 C275.1 FL8.3(OUT_IN) R92.2 R94.2 R96.2 R98.2 U14.AC7(XVDD1) U14.AC9(XVDD2) U14.AC12(XVDD3) U14.AC14(XVDD4) U14.AC17(XVDD5) U14.AC20(XVDD6) ; also on sheet 13
D1_ALERT_B: R142.2 U14.F28(D1_MALERT_B) U15.P9(~{ALERT}) U16.P9(~{ALERT}) U17.P9(~{ALERT}) U18.P9(~{ALERT}) U565.P9(~{ALERT})
D1_MA0: R111.1 U14.V27(D1_MA00) U15.P3(A0) U16.P3(A0) U17.P3(A0) U18.P3(A0) U565.P3(A0)
D1_MA1: R113.1 U14.N27(D1_MA01) U15.P7(A1) U16.P7(A1) U17.P7(A1) U18.P7(A1) U565.P7(A1)
D1_MA2: R112.1 U14.N28(D1_MA02) U15.R3(A2) U16.R3(A2) U17.R3(A2) U18.R3(A2) U565.R3(A2)
D1_MA3: R115.1 U14.M28(D1_MA03) U15.N7(A3) U16.N7(A3) U17.N7(A3) U18.N7(A3) U565.N7(A3)
D1_MA4: R114.1 U14.L28(D1_MA04) U15.N3(A4) U16.N3(A4) U17.N3(A4) U18.N3(A4) U565.N3(A4)
D1_MA5: R117.1 U14.L27(D1_MA05) U15.P8(A5) U16.P8(A5) U17.P8(A5) U18.P8(A5) U565.P8(A5)
D1_MA6: R116.1 U14.K28(D1_MA06) U15.P2(A6) U16.P2(A6) U17.P2(A6) U18.P2(A6) U565.P2(A6)
D1_MA7: R119.1 U14.J27(D1_MA07) U15.R8(A7) U16.R8(A7) U17.R8(A7) U18.R8(A7) U565.R8(A7)
D1_MA8: R118.1 U14.J28(D1_MA08) U15.R2(A8) U16.R2(A8) U17.R2(A8) U18.R2(A8) U565.R2(A8)
D1_MA9: R121.1 U14.G28(D1_MA09) U15.R7(A9) U16.R7(A9) U17.R7(A9) U18.R7(A9) U565.R7(A9)
D1_MA10: R120.1 U14.Y28(D1_MA10) U15.M3(A10/AP) U16.M3(A10/AP) U17.M3(A10/AP) U18.M3(A10/AP) U565.M3(A10/AP)
D1_MA11: R123.1 U14.H28(D1_MA11) U15.T2(A11) U16.T2(A11) U17.T2(A11) U18.T2(A11) U565.T2(A11)
D1_MA12: R122.1 U14.G27(D1_MA12) U15.M7(A12/~{BC}) U16.M7(A12/~{BC}) U17.M7(A12/~{BC}) U18.M7(A12/~{BC}) U565.M7(A12/~{BC})
D1_MA13: R124.1 U14.AD27(D1_MA13) U15.T8(A13) U16.T8(A13) U17.T8(A13) U18.T8(A13) U565.T8(A13)
D1_MACT_B: R133.1 U14.D28(D1_MACT_B) U15.L3(~{ACT}) U16.L3(~{ACT}) U17.L3(~{ACT}) U18.L3(~{ACT}) U565.L3(~{ACT})
D1_MBA0: R129.1 U14.Y27(D1_MBA0) U15.N2(BA0) U16.N2(BA0) U17.N2(BA0) U18.N2(BA0) U565.N2(BA0)
D1_MBA1: R128.1 U14.W28(D1_MBA1) U15.N8(BA1) U16.N8(BA1) U17.N8(BA1) U18.N8(BA1) U565.N8(BA1)
D1_MBG0: R130.1 U14.E27(D1_MBG0) U15.M2(BG0) U16.M2(BG0) U17.M2(BG0) U18.M2(BG0) U565.M2(BG0)
D1_MBG1: R132.1 U14.E28(D1_MBG1)
D1_MCAS_B: R125.1 U14.AC28(D1_MCAS_B) U15.M8(A15/~{CAS}) U16.M8(A15/~{CAS}) U17.M8(A15/~{CAS}) U18.M8(A15/~{CAS}) U565.M8(A15/~{CAS})
D1_MCKE0: R131.1 U14.C28(D1_MCKE0) U15.K2(CKE) U16.K2(CKE) U17.K2(CKE) U18.K2(CKE) U565.K2(CKE)
D1_MCLK0_N: R137.1 U14.R27(D1_MCK0_B) U15.K8(CK_C) U16.K8(CK_C) U17.K8(CK_C) U18.K8(CK_C) U565.K8(CK_C)
D1_MCLK0_P: R138.1 U14.R28(D1_MCK0) U15.K7(CK_T) U16.K7(CK_T) U17.K7(CK_T) U18.K7(CK_T) U565.K7(CK_T)
D1_MCS_B0: R136.1 U14.AB27(D1_MCS0_B) U15.L7(~{CS}) U16.L7(~{CS}) U17.L7(~{CS}) U18.L7(~{CS}) U565.L7(~{CS})
D1_MDIC_0: R141.2 U14.P28(D1_MDIC0)
D1_MDIC_1: R140.2 U14.U28(D1_MDIC1)
D1_MDM0: U14.B23(D1_MDM0) U15.E7(NF/~{LDM}/~{LDBI})
D1_MDM1: U14.H22(D1_MDM1) U15.E2(NF/~{UDM}/~{UDBI})
D1_MDM2: U14.E25(D1_MDM2) U16.E7(NF/~{LDM}/~{LDBI})
D1_MDM3: U14.J25(D1_MDM3) U16.E2(NF/~{UDM}/~{UDBI})
D1_MDM4: U14.V25(D1_MDM4) U17.E7(NF/~{LDM}/~{LDBI})
D1_MDM5: U14.AD24(D1_MDM5) U17.E2(NF/~{UDM}/~{UDBI})
D1_MDM6: U14.AC23(D1_MDM6) U18.E7(NF/~{LDM}/~{LDBI})
D1_MDM7: U14.AH24(D1_MDM7) U18.E2(NF/~{UDM}/~{UDBI})
D1_MDM8: U14.P24(D1_MDM8) U565.E7(NF/~{LDM}/~{LDBI})
D1_MDQ0: U14.C22(D1_MDQ00) U15.G2(DQ0)
D1_MDQ1: U14.A23(D1_MDQ01) U15.F7(DQ1)
D1_MDQ2: U14.C26(D1_MDQ02) U15.H3(DQ2)
D1_MDQ3: U14.A27(D1_MDQ03) U15.H7(DQ3)
D1_MDQ4: U14.B22(D1_MDQ04) U15.H2(DQ4)
D1_MDQ5: U14.A22(D1_MDQ05) U15.H8(DQ5)
D1_MDQ6: U14.B25(D1_MDQ06) U15.J3(DQ6)
D1_MDQ7: U14.A26(D1_MDQ07) U15.J7(DQ7)
D1_MDQ8: U14.E22(D1_MDQ08) U15.A3(DQ8)
D1_MDQ9: U14.D22(D1_MDQ09) U15.B8(DQ9)
D1_MDQ10: U14.F23(D1_MDQ10) U15.C3(DQ10)
D1_MDQ11: U14.G23(D1_MDQ11) U15.C7(DQ11)
D1_MDQ12: U14.G22(D1_MDQ12) U15.C2(DQ12)
D1_MDQ13: U14.F22(D1_MDQ13) U15.C8(DQ13)
D1_MDQ14: U14.C24(D1_MDQ14) U15.D3(DQ14)
D1_MDQ15: U14.E23(D1_MDQ15) U15.D7(DQ15)
D1_MDQ16: U14.D26(D1_MDQ16) U16.G2(DQ0)
D1_MDQ17: U14.E24(D1_MDQ17) U16.F7(DQ1)
D1_MDQ18: U14.G24(D1_MDQ18) U16.H3(DQ2)
D1_MDQ19: U14.H25(D1_MDQ19) U16.H7(DQ3)
D1_MDQ20: U14.C25(D1_MDQ20) U16.H2(DQ4)
D1_MDQ21: U14.D25(D1_MDQ21) U16.H8(DQ5)
D1_MDQ22: U14.G25(D1_MDQ22) U16.J3(DQ6)
D1_MDQ23: U14.H26(D1_MDQ23) U16.J7(DQ7)
D1_MDQ24: U14.K23(D1_MDQ24) U16.A3(DQ8)
D1_MDQ25: U14.J24(D1_MDQ25) U16.B8(DQ9)
D1_MDQ26: U14.L24(D1_MDQ26) U16.C3(DQ10)
D1_MDQ27: U14.M24(D1_MDQ27) U16.C7(DQ11)
D1_MDQ28: U14.J22(D1_MDQ28) U16.C2(DQ12)
D1_MDQ29: U14.H23(D1_MDQ29) U16.C8(DQ13)
D1_MDQ30: U14.K24(D1_MDQ30) U16.D3(DQ14)
D1_MDQ31: U14.L25(D1_MDQ31) U16.D7(DQ15)
D1_MDQ32: U14.V24(D1_MDQ32) U17.G2(DQ0)
D1_MDQ33: U14.U26(D1_MDQ33) U17.F7(DQ1)
D1_MDQ34: U14.AA26(D1_MDQ34) U17.H3(DQ2)
D1_MDQ35: U14.W23(D1_MDQ35) U17.H7(DQ3)
D1_MDQ36: U14.U24(D1_MDQ36) U17.H2(DQ4)
D1_MDQ37: U14.U25(D1_MDQ37) U17.H8(DQ5)
D1_MDQ38: U14.W24(D1_MDQ38) U17.J3(DQ6)
D1_MDQ39: U14.Y25(D1_MDQ39) U17.J7(DQ7)
D1_MDQ40: U14.AB24(D1_MDQ40) U17.A3(DQ8)
D1_MDQ41: U14.AB25(D1_MDQ41) U17.B8(DQ9)
D1_MDQ42: U14.AE25(D1_MDQ42) U17.C3(DQ10)
D1_MDQ43: U14.AF25(D1_MDQ43) U17.C7(DQ11)
D1_MDQ44: U14.Y24(D1_MDQ44) U17.C2(DQ12)
D1_MDQ45: U14.AA25(D1_MDQ45) U17.C8(DQ13)
D1_MDQ46: U14.AD25(D1_MDQ46) U17.D3(DQ14)
D1_MDQ47: U14.AE26(D1_MDQ47) U17.D7(DQ15)
D1_MDQ48: U14.AA22(D1_MDQ48) U18.G2(DQ0)
D1_MDQ49: U14.AB23(D1_MDQ49) U18.F7(DQ1)
D1_MDQ50: U14.AC22(D1_MDQ50) U18.H3(DQ2)
D1_MDQ51: U14.AB22(D1_MDQ51) U18.H7(DQ3)
D1_MDQ52: U14.Y22(D1_MDQ52) U18.H2(DQ4)
D1_MDQ53: U14.AA23(D1_MDQ53) U18.H8(DQ5)
D1_MDQ54: U14.AD22(D1_MDQ54) U18.J3(DQ6)
D1_MDQ55: U14.AE22(D1_MDQ55) U18.J7(DQ7)
D1_MDQ56: U14.AH25(D1_MDQ56) U18.A3(DQ8)
D1_MDQ57: U14.AF24(D1_MDQ57) U18.B8(DQ9)
D1_MDQ58: U14.AG22(D1_MDQ58) U18.C3(DQ10)
D1_MDQ59: U14.AF22(D1_MDQ59) U18.C7(DQ11)
D1_MDQ60: U14.AH26(D1_MDQ60) U18.C2(DQ12)
D1_MDQ61: U14.AG25(D1_MDQ61) U18.C8(DQ13)
D1_MDQ62: U14.AF23(D1_MDQ62) U18.D3(DQ14)
D1_MDQ63: U14.AH22(D1_MDQ63) U18.D7(DQ15)
D1_MDQS0_N: U14.A24(D1_MDQS0_B) U15.F3(LDQS_C)
D1_MDQS0_P: U14.A25(D1_MDQS0) U15.G3(LDQS_T)
D1_MDQS1_N: U14.C23(D1_MDQS1_B) U15.A7(UDQS_C)
D1_MDQS1_P: U14.D23(D1_MDQS1) U15.B7(UDQS_T)
D1_MDQS2_N: U14.F26(D1_MDQS2_B) U16.F3(LDQS_C)
D1_MDQS2_P: U14.F25(D1_MDQS2) U16.G3(LDQS_T)
D1_MDQS3_N: U14.K25(D1_MDQS3_B) U16.A7(UDQS_C)
D1_MDQS3_P: U14.K26(D1_MDQS3) U16.B7(UDQS_T)
D1_MDQS4_N: U14.W25(D1_MDQS4_B) U17.F3(LDQS_C)
D1_MDQS4_P: U14.W26(D1_MDQS4) U17.G3(LDQS_T)
D1_MDQS5_N: U14.AC26(D1_MDQS5_B) U17.A7(UDQS_C)
D1_MDQS5_P: U14.AC25(D1_MDQS5) U17.B7(UDQS_T)
D1_MDQS6_N: U14.AD23(D1_MDQS6_B) U18.F3(LDQS_C)
D1_MDQS6_P: U14.AE23(D1_MDQS6) U18.G3(LDQS_T)
D1_MDQS7_N: U14.AG23(D1_MDQS7_B) U18.A7(UDQS_C)
D1_MDQS7_P: U14.AH23(D1_MDQS7) U18.B7(UDQS_T)
D1_MDQS8_N: U14.P26(D1_MDQS8_B) U565.F3(LDQS_C)
D1_MDQS8_P: U14.P25(D1_MDQS8) U565.G3(LDQS_T)
D1_MECC0: U14.M26(D1_MECC0) U565.G2(DQ0)
D1_MECC1: U14.N25(D1_MECC1) U565.F7(DQ1)
D1_MECC2: U14.T25(D1_MECC2) U565.H3(DQ2)
D1_MECC3: U14.T24(D1_MECC3) U565.H7(DQ3)
D1_MECC4: U14.M25(D1_MECC4) U565.H2(DQ4)
D1_MECC5: U14.N24(D1_MECC5) U565.H8(DQ5)
D1_MECC6: U14.R25(D1_MECC6) U565.J3(DQ6)
D1_MECC7: U14.R24(D1_MECC7) U565.J7(DQ7)
D1_MODT0: R135.1 U14.AD28(D1_MODT0) U15.K3(ODT) U16.K3(ODT) U17.K3(ODT) U18.K3(ODT) U565.K3(ODT)
D1_MRAS_B: R127.1 U14.AA28(D1_MRAS_B) U15.L8(A16/~{RAS}) U16.L8(A16/~{RAS}) U17.L8(A16/~{RAS}) U18.L8(A16/~{RAS}) U565.L8(A16/~{RAS})
D1_MWE_B: R126.1 U14.AB28(D1_MWE_B) U15.L2(A14/~{WE}) U16.L2(A14/~{WE}) U17.L2(A14/~{WE}) U18.L2(A14/~{WE}) U565.L2(A14/~{WE})
D1_PAROUT: R134.1 U14.V28(D1_MPAR) U15.T3(PAR) U16.T3(PAR) U17.T3(PAR) U18.T3(PAR) U565.T3(PAR)
DDR4_CLK_TERM: C431.2 R137.2 R138.2
DDR4_ZQ0: R105.1 U17.F9(ZQ)
DDR4_ZQ1: R106.1 U18.F9(ZQ)
DDR4_ZQ2: R103.1 U15.F9(ZQ)
DDR4_ZQ3: R104.1 U16.F9(ZQ)
DDR4_ZQ5: R107.1 U565.F9(ZQ)
DDR_VREF1: C1406.1 R960.2 R961.1 U15.M1(VREFCA)
DDR_VREF2: C1430.1 R962.2 R963.1 U16.M1(VREFCA)
DDR_VREF3: C669.1 R954.2 R955.1 U17.M1(VREFCA)
DDR_VREF4: C1382.1 R956.2 R957.1 U18.M1(VREFCA)
DDR_VREF5: C1577.1 R958.2 R959.1 U565.M1(VREFCA)
DDR_VTT: C402.1 C403.1 C408.1 C409.1 C410.1 C1352.1 C1353.1 C1354.1 C1355.1 C1356.1 C1357.1 C1358.1 C1359.1 C1360.1 C1584.1 C1585.1 R111.2 R112.2 R113.2 R114.2 R115.2 R116.2 R117.2 R118.2 R119.2 R120.2 R121.2 R122.2 R123.2 R124.2 R125.2 R126.2 R127.2 R128.2 R129.2 R130.2 R131.2 R132.2 R133.2 R134.2 R135.2 R136.2 ; also on sheet 6
FA_VL: C337.1 C338.1 J12.2 R102.1 U14.AB21(FA_VL) ; also on sheet 8
FTM7_CH0: U14.A19(IFC_CS1_B) ; also on sheet 19
FUSE_PWR_STATUS#: U566.4(Y) ; also on sheet 17
GPIO_FUSE_PROG: R412.1 U549.6(2B) ; also on sheet 18
GVDD: C279.1 C280.1 C281.1 C282.1 C283.1 C284.1 C285.1 C286.1 C287.1 C288.1 C289.1 C303.1 C304.1 C305.1 C306.1 C307.1 C308.1 C309.1 C310.1 C311.1 C312.1 C313.1 C314.1 C315.1 C316.1 C317.1 C318.1 C319.1 C320.1 C321.1 C322.1 C323.1 C324.1 C364.1 C365.1 C366.1 C367.1 C374.1 C375.1 C383.1 C384.1 C402.2 C403.2 C408.2 C409.2 C410.2 C431.1 C517.1 C518.1 C519.1 C520.1 C521.1 C522.1 C523.1 C524.1 C668.1 C1349.1 C1350.1 C1351.1 C1352.2 C1353.2 C1354.2 C1355.2 C1356.2 C1357.2 C1358.2 C1359.2 C1360.2 C1361.1 C1362.1 C1363.1 C1364.1 C1365.1 C1366.1 C1367.1 C1368.1 C1369.1 C1370.1 C1371.1 C1372.1 C1373.1 C1374.1 C1375.1 C1376.1 C1377.1 C1378.1 C1379.1 C1380.1 C1385.1 C1386.1 C1387.1 C1388.1 C1389.1 C1390.1 C1391.1 C1392.1 C1393.1 C1394.1 C1395.1 C1396.1 C1397.1 C1398.1 C1399.1 C1400.1 C1401.1 C1402.1 C1403.1 C1404.1 C1409.1 C1410.1 C1411.1 C1412.1 C1413.1 C1414.1 C1415.1 C1416.1 C1417.1 C1418.1 C1419.1 C1420.1 C1421.1 C1422.1 C1423.1 C1424.1 C1425.1 C1426.1 C1427.1 C1428.1 C1556.1 C1557.1 C1558.1 C1559.1 C1560.1 C1561.1 C1562.1 C1563.1 C1564.1 C1565.1 C1566.1 C1567.1 C1568.1 C1569.1 C1570.1 C1571.1 C1572.1 C1573.1 C1574.1 C1575.1 C1586.1 R82.1 R83.1 R140.1 R142.1 R954.1 R956.1 R958.1 R960.1 R962.1 U14.AA27(G1VDD18) U14.AC27(G1VDD19) U14.AE27(G1VDD20) U14.AG27(G1VDD21) U14.AH27(G1VDD22) U14.B27(G1VDD01) U14.D27(G1VDD02) U14.F27(G1VDD03) U14.H27(G1VDD04) U14.K27(G1VDD05) U14.L22(G1VDD06) U14.M22(G1VDD07) U14.M27(G1VDD08) U14.N22(G1VDD09) U14.P22(G1VDD10) U14.P27(G1VDD11) U14.R22(G1VDD12) U14.T22(G1VDD13) U14.U22(G1VDD14) U14.U27(G1VDD15) U14.V22(G1VDD16) U14.W27(G1VDD17) U15.A1(VDDQ1) U15.A9(VDDQ2) U15.B3(VDD1) U15.B9(VDD2) U15.C1(VDDQ3) U15.D1(VDD3) U15.D9(VDDQ4) U15.F2(VDDQ5) U15.F8(VDDQ6) U15.G1(VDDQ7) U15.G7(VDD4) U15.G9(VDDQ8) U15.J1(VDD5) U15.J2(VDDQ9) U15.J8(VDDQ10) U15.J9(VDD6) U15.L1(VDD7) U15.L9(VDD8) U15.R1(VDD9) U15.T9(VDD10) U16.A1(VDDQ1) U16.A9(VDDQ2) U16.B3(VDD1) U16.B9(VDD2) U16.C1(VDDQ3) U16.D1(VDD3) U16.D9(VDDQ4) U16.F2(VDDQ5) U16.F8(VDDQ6) U16.G1(VDDQ7) U16.G7(VDD4) U16.G9(VDDQ8) U16.J1(VDD5) U16.J2(VDDQ9) U16.J8(VDDQ10) U16.J9(VDD6) U16.L1(VDD7) U16.L9(VDD8) U16.R1(VDD9) U16.T9(VDD10) U17.A1(VDDQ1) U17.A9(VDDQ2) U17.B3(VDD1) U17.B9(VDD2) U17.C1(VDDQ3) U17.D1(VDD3) U17.D9(VDDQ4) U17.F2(VDDQ5) U17.F8(VDDQ6) U17.G1(VDDQ7) U17.G7(VDD4) U17.G9(VDDQ8) U17.J1(VDD5) U17.J2(VDDQ9) U17.J8(VDDQ10) U17.J9(VDD6) U17.L1(VDD7) U17.L9(VDD8) U17.R1(VDD9) U17.T9(VDD10) U18.A1(VDDQ1) U18.A9(VDDQ2) U18.B3(VDD1) U18.B9(VDD2) U18.C1(VDDQ3) U18.D1(VDD3) U18.D9(VDDQ4) U18.F2(VDDQ5) U18.F8(VDDQ6) U18.G1(VDDQ7) U18.G7(VDD4) U18.G9(VDDQ8) U18.J1(VDD5) U18.J2(VDDQ9) U18.J8(VDDQ10) U18.J9(VDD6) U18.L1(VDD7) U18.L9(VDD8) U18.R1(VDD9) U18.T9(VDD10) U565.A1(VDDQ1) U565.A9(VDDQ2) U565.B3(VDD1) U565.B9(VDD2) U565.C1(VDDQ3) U565.D1(VDD3) U565.D9(VDDQ4) U565.F2(VDDQ5) U565.F8(VDDQ6) U565.G1(VDDQ7) U565.G7(VDD4) U565.G9(VDDQ8) U565.J1(VDD5) U565.J2(VDDQ9) U565.J8(VDDQ10) U565.J9(VDD6) U565.L1(VDD7) U565.L9(VDD8) U565.R1(VDD9) U565.T9(VDD10) ; also on sheet 6 18
IFC_AD0: U14.B8(IFC_AD00) U522.J8(I/O7)
IFC_AD1: U14.A8(IFC_AD01) U522.K7(I/O6)
IFC_AD2: U14.B9(IFC_AD02) U522.J7(I/O5)
IFC_AD3: U14.A9(IFC_AD03) U522.K6(I/O4)
IFC_AD4: U14.A10(IFC_AD04) U522.K5(I/O3)
IFC_AD5: U14.B11(IFC_AD05) U522.K4(I/O2)
IFC_AD6: U14.A11(IFC_AD06) U522.J4(I/O1)
IFC_AD7: U14.B12(IFC_AD07) U522.H4(I/O0)
IFC_AD8: S1.20(B1) U14.A12(IFC_AD08)
IFC_AD9: S1.19(B2) U14.A13(IFC_AD09)
IFC_AD10: S1.18(B3) U14.B14(IFC_AD10)
IFC_AD11: S1.17(B4) U14.A14(IFC_AD11)
IFC_AD12: S1.16(B5) U14.B15(IFC_AD12)
IFC_AD13: S1.15(B6) U14.A15(IFC_AD13)
IFC_AD14: S1.14(B7) U14.A16(IFC_AD14)
IFC_AD15: S1.13(B8) U14.A17(IFC_AD15)
IFC_AVD: R873.1 U14.A18(IFC_AVD) U522.C4(ALE)
IFC_CLE: S1.12(B9) U14.C19(IFC_CLE) U522.D5(CLE)
IFC_OE_B: R203.2 U14.C18(IFC_OE_B) U522.D4(~{RE})
IFC_RB0_B: R204.2 U14.C16(IFC_RB0_B) U522.C8(R/~{B})
IFC_RB1_B: R205.2 U14.D16(IFC_RB1_B)
IFC_TE: R814.1 U14.E14(IFC_TE)
IFC_WE_B: S1.11(B10) U14.C15(IFC_WE0_B) U522.C7(~{WE})
IFC_WP_B: U14.D19(IFC_WP0_B) U522.C3(~{WP})
NAND_CS_B: R737.2 U14.C17(IFC_CS0_B) U522.C6(~{CE})
OVDD: C290.1 C291.1 C292.1 C293.1 C294.1 C295.1 C296.1 C297.1 C336.1 C1248.1 C1249.1 C1251.1 C1295.1 C1296.1 C1318.1 C1433.1 J11.2 J74.1 L56.1 R91.1 R93.1 R95.1 R97.1 R203.1 R204.1 R205.1 R737.1 R809.1 R810.1 R811.1 R814.2 R815.2 R816.2 R873.2 R947.1 U14.G8(TH_VDD) U14.J14(OVDD1) U14.J15(OVDD2) U14.J16(OVDD3) U14.J17(OVDD4) U14.J18(OVDD5) U14.R7(OVDD6) U522.D3(VCC1) U522.G4(VCC2) U522.H8(VCC3) U522.J6(VCC4) U532.2(VCC) U549.8(VCCB) ; also on sheet 6 13 15 16 17 18 19
PORESET_B: U532.3(~{RESET}/DNU1) ; also on sheet 16 18
PROG_SFP_EN: R409.2 U549.3(2A) U566.2(A)
PROG_SFP_Y_EN: Q3.1(GATE) R409.1
PWR_PROG_MTR: C328.1 J11.1 R100.1 U14.F13(PROG_MTR)
PWR_PROG_SFP: C329.1 J74.2 Q3.2(SOURCE) R101.1 U14.G13(TA_PROG_SFP)
QSPI_A_CS0: R809.2 U14.D8(IFC_A16) U532.7(~{S})
QSPI_A_DATA0: U14.D11(IFC_A22) U532.15(DQ0)
QSPI_A_DATA1: U14.C12(IFC_A23) U532.8(DQ1)
QSPI_A_DATA2: R810.2 U14.D13(IFC_A24) U532.9(~{W}/DQ2)
QSPI_A_DATA3: R811.2 U14.C13(IFC_A25) U532.1(~{HOLD}/DQ3)
QSPI_A_SCK: U14.C9(IFC_A18) U532.16(C)
RST_MEM_B: U15.P1(~{RESET}) U16.P1(~{RESET}) U17.P1(~{RESET}) U18.P1(~{RESET}) U565.P1(~{RESET}) ; also on sheet 18
SYS_STATUS#: U14.E17(IFC_PERR_B) U549.7(1B)
SYS_STATUS_LT#: U549.2(1A) ; also on sheet 17
N28196038: R82.2 U565.E2(NF/~{UDM}/~{UDBI})
N28196089: R83.2 U565.A7(UDQS_C)
N28196104: R84.2 U565.B7(UDQS_T)
N28397648: Q3.3(DRAIN) R947.2

Not connected (* = marked no-connect by the designer): U14 A20(IFC_CLK0)* AE28(D1_MCS1_B)* AF27(D1_MODT1)* AF28(D1_MCS3_B)* AG28(D1_MCS2_B)* B17(IFC_NDDQS)* B20(IFC_CLK1)* B28(D1_MCKE1)* C8(IFC_A17) C10(IFC_A20)* C14(IFC_A27)* C20(IFC_CS3_B)* D10(IFC_A19)* D14(IFC_A26)* D20(IFC_CS2_B)* E15(IFC_BCTL)* E16(IFC_NDDDR_CLK)* F21(D1_TPA)* H8(TH_TPA)* T27(D1_MCK1_B)* T28(D1_MCK1)*; U15 T7(NC)*; U16 T7(NC)*; U17 T7(NC)*; U18 T7(NC)*; U522 A1(NC)* A2(NC)* A9(NC)* A10(NC)* B1(NC)* B9(NC)* B10(NC)* D6(NC)* D7(NC)* D8(NC)* E3(NC)* E4(NC)* E5(NC)* E6(NC)* E7(NC)* E8(NC)* F3(NC)* F4(NC)* F5(NC)* F6(NC)* F8(NC)* G3(NC)* G5(NC)* G6(NC)* G7(NC)* G8(NC)* H3(NC)* H5(NC)* H6(NC)* H7(NC)* J3(NC)* J5(NC)* L1(NC)* L2(NC)* L9(NC)* L10(NC)* M1(NC)* M2(NC)* M9(NC)* M10(NC)*; U532 4(DNU2)* 5(DNU3)* 6(DNU4)* 11(DNU5)* 12(DNU6)* 13(DNU7)* 14(DNU8)*; U565 A3(DQ8) B8(DQ9) C2(DQ12) C3(DQ10) C7(DQ11) C8(DQ13) D3(DQ14) D7(DQ15) T7(NC)*; U566 1(NC)*

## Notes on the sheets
sheet 9
- ->
- ->
- GPIO_FUSE_PROG is High, Q3 is ON=  PROG_SFP=1.8V {Fuse programming Enable}
  GPIO_FUSE_PROG is Low, Q3 is OFF=  PROG_SFP=0V {Fuse programming Disable} -> Default
- (Normally Open)
- (Normally Open)
sheet 10
- BYTE 0
- (Nibble ECC for LS1043)
- BYTE 1
- (Byte 3 for LS1043)
- BYTE 2
- (Byte 2 for LS1043)
- BYTE 3
- (Byte 1 for LS1043)
sheet 11
- BYTE 4
- ECC BYTE for LS1046
- (NU for LS1043)
- BYTE 5
- BYTE 0 for LS1043
- (NU for LS1043)
- BYTE 6
- (NU for LS1043)
- BYTE 7
- (NU for LS1043)
- Clock, control, command, and address line terminations:
sheet 12
- SW1[1:9]=> CFG_RCW_SRC[0:8]
  ##    0_0100_0100                   (Quad SPI) – default
  ##    0_0100_0000                   (eSDHC)
  ##    1_0000_01xx                   (8-bit NAND , 2 KB page, 64 pages/block) [LS1043 only)***
  ##    0_1001_1110                   (0x9E - Hard-Coded RCW)
  Note:: LS1046A do not support booting from NAND flash
- CPU BOOT SOURCE and POR CONFIG
- SW1[10]=> CFG_ENG_USE0
  #  0    DIFF_SYSCLK/DIFF_SYSCLK_B (differential)-> 100MHz (Fixed) – default
  #  1    SYSCLK (single ended)-> 100MHz (Fixed)
- ON
- cfg_rcw_src0
- cfg_eng_use0
- cfg_rcw_src1
- cfg_rcw_src8
- cfg_rcw_src2
- cfg_rcw_src3
- cfg_eng_use1
- cfg_rcw_src4
- cfg_rcw_src5
- cfg_rcw_src6
- cfg_rcw_src7
- cfg_eng_use2
- cfg_rsp_dis
- cfg_ifc_te
- cfg_svr[0]
- cfg_svr[1]
- cfg_pll_config_sel_b
- cfg_por_ainit
- cfg_test_port_dis
- RCW Settings:
  IFC_GRP_A_EXT                             001
  IFC_GRP_D_EXT                             000
  FC_GRP_E1_EXT                             000
  IFC_GRP_F_EXT                             001
  IFC_GRP_E1_BASE                         1 {GPIO2[10:12]}
  IFC_GRP_D_BASE                            1 {GPIO2[13:15]}
- cfg_dram_type
- GPIO2[15]
- GPIO2[13]
- GPIO2[14]
- PCB Revisioin: BRD_REV[1:0]
  00       RevA
  01       RevB
- NAND Flash
  4Gb(512Mx8)
- QSPI FLASH
  64MB
